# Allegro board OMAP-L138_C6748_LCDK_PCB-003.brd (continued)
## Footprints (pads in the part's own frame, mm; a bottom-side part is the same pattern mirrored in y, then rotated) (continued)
QFN48_25V
  custom 0.058x0.058 smd: 1(-2.75,-3.475) 2(-2.25,-3.475) 3(-1.75,-3.475) 4(-1.25,-3.475) 5(-0.75,-3.475) 6(-0.25,-3.475) 7(0.25,-3.475) 8(0.75,-3.475) 9(1.25,-3.475) 10(1.75,-3.475) 11(2.25,-3.475) 12(2.75,-3.475) 13(3.475,-2.75) 14(3.475,-2.25) 15(3.475,-1.75) 16(3.475,-1.25) 17(3.475,-0.75) 18(3.475,-0.25) 19(3.475,0.25) 20(3.475,0.75) 21(3.475,1.25) 22(3.475,1.75) 23(3.475,2.25) 24(3.475,2.75) 25(2.75,3.475) 26(2.25,3.475) 27(1.75,3.475) 28(1.25,3.475) 29(0.75,3.475) 30(0.25,3.475) 31(-0.25,3.475) 32(-0.75,3.475) 33(-1.25,3.475) 34(-1.75,3.475) 35(-2.25,3.475) 36(-2.75,3.475) 37(-3.475,2.75) 38(-3.475,2.25) 39(-3.475,1.75) 40(-3.475,1.25) 41(-3.475,0.75) 42(-3.475,0.25) 43(-3.475,-0.25) 44(-3.475,-0.75) 45(-3.475,-1.25) 46(-3.475,-1.75) 47(-3.475,-2.25) 48(-3.475,-2.75)
  rect 5.156x5.156 smd: 49(0,0)
RAPC712
  round 4.064 hole 3.556: 1(0,0)
  round 3.683 hole 3.048: 2(-2.997,-4.801) 3(-6.248,0)
RCA4SMD_11X15MM
  round 3.175 hole 1.803: 1(0,0)
  rect 2.54x2.286 smd: 2(0,-6.25) 3(-6.35,-6) 4(6.35,-6)
RJ45-2LED
  round 3.251 hole 3.251 unplated: (8.89,1.27) (8.89,-10.16)
  rect 1.397x1.397 hole 0.889: 1(0,0)
  round 1.397 hole 0.889: 2(2.54,-1.27) 3(0,-2.54) 4(2.54,-3.81) 5(0,-5.08) 6(2.54,-6.35) 7(0,-7.62) 8(2.54,-8.89)
  round 1.524 hole 1.016: 9(-4.826,1.016) 10(-4.826,-1.524) 11(-4.826,-7.366) 12(-4.826,-9.906)
  round 2.54 hole 1.575: 13(5.842,3.302) 14(5.842,-12.192)
SATA
  rect 1.27x1.27 hole 0.762: 1(7.91,0)
  oval 1.016x1.27 hole 0.762: 2(6.64,1.5) 3(5.37,1.5) 5(2.83,1.5) 6(1.56,1.5)
  round 1.27 hole 0.762: 4(4.1,0) 7(0.29,0)
  round 2.032 hole 1.397: 8(10.37,1.5) 9(-2.46,2.5)
SD-MICRO-SCHA5B0300
  rect 0.914x0.457 smd: 1(-7.257,0) 2(-7.257,-0.7) 3(-7.257,-1.4) 4(-7.257,-2.1) 5(7.257,-2.1) 6(7.257,-1.4) 7(7.257,-0.7) 8(7.257,0)
  rect 0.508x0.889 smd: 9(3.775,9.989) 10(-5.975,9.989)
  rect 0.889x2.007 smd: 11(-7.25,7.635) 12(7.25,6.335)
  rect 1.118x1.524 smd: 13(-7.196,-3.365) 14(7.196,-3.365)
  rect 1.194x1.092 smd: 15(-3.425,10.488) 16(2.575,10.488)
SM_OSC_ABM3
  rect 1.9x2.4 smd: 1(-2.05,0) 2(2.05,0)
SMINI6-F3-B
  rect 0.305x0.95 smd: 1(0.65,0.75) 2(0,0.75) 3(-0.65,0.75) 4(-0.65,-0.75) 5(0,-0.75) 6(0.65,-0.75)
SOIC8
  rect 0.635x1.905 smd: 1(-1.905,-2.73) 2(-0.635,-2.73) 3(0.635,-2.73) 4(1.905,-2.73) 5(1.905,2.73) 6(0.635,2.73) 7(-0.635,2.73) 8(-1.905,2.73)
SOIC16
  rect 1.27x0.635 smd: 1(-2.477,4.445) 2(-2.477,3.175) 3(-2.477,1.905) 4(-2.477,0.635) 5(-2.477,-0.635) 6(-2.477,-1.905) 7(-2.477,-3.175) 8(-2.477,-4.445) 9(2.477,-4.445) 10(2.477,-3.175) 11(2.477,-1.905) 12(2.477,-0.635) 13(2.477,0.635) 14(2.477,1.905) 15(2.477,3.175) 16(2.477,4.445)
SOP-DGG48
  rect 0.254x1.651 smd: 1(-5.75,-3.813) 2(-5.25,-3.813) 3(-4.75,-3.813) 4(-4.25,-3.813) 5(-3.75,-3.813) 6(-3.25,-3.813) 7(-2.75,-3.813) 8(-2.25,-3.813) 9(-1.75,-3.813) 10(-1.25,-3.813) 11(-0.75,-3.813) 12(-0.25,-3.813) 13(0.25,-3.813) 14(0.75,-3.813) 15(1.25,-3.813) 16(1.75,-3.813) 17(2.25,-3.813) 18(2.75,-3.813) 19(3.25,-3.813) 20(3.75,-3.813) 21(4.25,-3.813) 22(4.75,-3.813) 23(5.25,-3.813) 24(5.75,-3.813) 25(5.75,3.813) 26(5.25,3.813) 27(4.75,3.813) 28(4.25,3.813) 29(3.75,3.813) 30(3.25,3.813) 31(2.75,3.813) 32(2.25,3.813) 33(1.75,3.813) 34(1.25,3.813) 35(0.75,3.813) 36(0.25,3.813) 37(-0.25,3.813) 38(-0.75,3.813) 39(-1.25,3.813) 40(-1.75,3.813) 41(-2.25,3.813) 42(-2.75,3.813) 43(-3.25,3.813) 44(-3.75,3.813) 45(-4.25,3.813) 46(-4.75,3.813) 47(-5.25,3.813) 48(-5.75,3.813)
SOT23_3
  rect 0.813x1.016 smd: 1(-0.95,-1) 2(0.95,-1) 3(0,1)
STX3500
  round 1.702 hole 1.702 unplated: (-3.75,0) (3.25,0)
  rect 2.21x2.794 smd: 1(-4.85,-3.7) 3(-2.85,3.7)
  rect 2.794x2.794 smd: 2(4.55,-3.7) 4(8.65,0.75)
SWDIP16_340SMD
  rect 1.143x2.54 smd: 1(-8.89,-4.318) 2(-6.35,-4.318) 3(-3.81,-4.318) 4(-1.27,-4.318) 5(1.27,-4.318) 6(3.81,-4.318) 7(6.35,-4.318) 8(8.89,-4.318) 9(8.89,4.318) 10(6.35,4.318) 11(3.81,4.318) 12(1.27,4.318) 13(-1.27,4.318) 14(-3.81,4.318) 15(-6.35,4.318) 16(-8.89,4.318)
SWRST4_177X256LS-1
  round 2.032 hole 1.067: 1(-3.251,-2.248) 2(3.251,-2.248) 3(-3.251,2.248) 4(3.251,2.248)
TP
  round 1.422 hole 1.016: 1(0,0)
unnamed#2
  round 1.016 smd: 1(0,0)
USB5MINI_4SHIELDED_SMD-4
  rect 2.25x0.5 smd: 1(0,1.6) 2(0,0.8) 3(0,0) 4(0,-0.8) 5(0,-1.6)
  rect 3.5x2.05 smd: 6(0.025,4.916) 9(0.025,-4.916)
  rect 4x2.05 smd: 7(-4.225,4.916) 8(-4.225,-4.916)
USB_A_SH
  round 1.651 hole 1.016: 1(0,0) 2(2.499,0) 3(4.501,0) 4(7,0)
  oval 2.032x3.429 hole 1.016x2.413: 5(-3.071,-2.71) 6(10.071,-2.71)
XTAL2_FX135
  rect 1.143x2.032 smd: 1(-1.245,0) 2(1.245,0)
XTAL4_74X83LS_98X126SMD
  rect 1.016x0.889 smd: 1(-1.05,-0.95) 2(1.05,-0.95) 3(1.05,0.95) 4(-1.05,0.95)

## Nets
1V2_LDO: C17.1 C66.1 C67.1 C68.1 C69.1 FB4.1 R20.1 U3.16(VLDO1) U7.M2(SATA_VDD0) U7.M12(USB_CVDD12) U7.N4(SATA_VDD3) U7.P1(SATA_VDD1) U7.P2(SATA_VDD2)
1V8_LDO: C16.2 C64.1 C65.1 R18.2 U3.14(VLDO2) U7.N14(USB0_VDDA18) U7.P3(SATA_VDDR) U7.P14(USB1_VDDA18)
5V_IN: D1.3(C) D2.2(ANODE) J1.1 J8.9 J14.1 J14.2(21) J15.24(32) J15.33(17) J15.45 J15.46 J16.4 J16.5 P1.1 P1.2 R270.1 U2.1(IN1) U2.7(IN0)
GND_EARTH: FB5.1 J2.6(G3) J2.7(G2) J2.8(G5) J2.9(G4) J3.6(G3) J3.7(G2) J3.8(G5) J3.9(G4) J4.11(GND3) J4.12(GND4) J4.13(GND5) J4.14(GND6) J4.15(GND7) J4.16(GND8) J5.5(SHELD1) J5.6(PAD4) J7.8(MH1) J7.9(MH2)
VCC_1V2A: FB4.2 U7.L15(VDDA12_PLL0) U7.N15(VDDA12_PLL1)
VCC_1V3D: C11.1 C12.1 C70.1 C71.1 C72.1 C73.1 C74.1 C75.1 C76.1 C77.1 C78.1 C79.1 C80.1 R5.2(I2) R27.1 R29.1 TP2.1 U7.E5(RVDD-0) U7.E15(CVDD-0) U7.G7(CVDD-1) U7.G8(CVDD-2) U7.G13(CVDD-3) U7.H6(CVDD-4) U7.H7(CVDD-5) U7.H10(CVDD-6) U7.H11(CVDD-7) U7.H12(CVDD-8) U7.H13(CVDD-9) U7.H14(RVDD-1) U7.J6(CVDD-10) U7.J12(CVDD-11) U7.K6(CVDD-12) U7.K12(CVDD-13) U7.L12(CVDD-14) U7.M8(CVDD-15) U7.M9(CVDD-16) U7.N7(RVDD-2) U7.N8(CVDD-17) U7.T19(VPP(RSV))
VCC_1V8D: C5.1 C6.1 C35.1 C36.1 C37.1 C38.1 C39.1 C40.1 C41.1 C42.1 C43.1 C44.1 C45.1 C94.1 C101.2 C102.2 C103.2 C119.2 C120.1 C121.1 C122.1 C123.1 C124.1 C125.1 C126.1 C127.1 C128.1 C129.1 C130.1 C131.1 C132.1 C133.1 C134.1 C135.1 C152.1 C153.1 C154.1 C155.1 C156.1 C170.1 C171.1 C204.1 C207.2 C208.2 C210.1 C216.2 FB10.1 FB15.2 P2.2 R2.2(I2) R28.1 R98.2 R99.2 R100.2 R123.1 TP4.1 U7.F14(DVDD18-0) U7.G6(DVDD18-1) U7.G10(DVDD18-2) U7.G11(DVDD18-3) U7.G12(DVDD18-4) U7.J13(DVDD18-5) U7.K5(DVDD18-6) U7.L6(DVDD18-7) U7.N6(DVDD18-8) U7.N9(DVDD18-9) U7.N10(DVDD18-10) U7.P7(DVDD18-11) U7.P8(DVDD18-12) U7.P9(DVDD18-13) U7.P10(DVDD18-14) U7.P13(DVDD18-15) U7.R7(DVDD18-16) U7.R8(DVDD18-17) U7.R9(DVDD18-18) U7.R13(DVDD18-19) U12.1(VCCA) U13.12(DVDD) U14.31(VCCA1) U14.42(VCCA2) U17.A1(VDD5) U17.A9(VDDQ10) U17.C1(VDDQ9) U17.C3(VDDQ8) U17.C7(VDDQ7) U17.C9(VDDQ6) U17.E1(VDD4) U17.E9(VDDQ4) U17.G1(VDDQ3) U17.G3(VDDQ5) U17.G7(VDDQ2) U17.G9(VDDQ1) U17.J1(VDDL) U17.J9(VDD1) U17.M9(VDD3) U17.R1(VDD2) U21.31(DVDD4) U21.41(DVDD5) U21.55(DVDD6) U21.67(DVDD7) U24.1(VCCA) U25.3(VCCA) U25.6(OE) U26.A2(VDDA) U26.E4(VDD) U28.1(VCCA) U28.5(DIR)
VCC_3V3A: C199.1 C200.1 C201.1 FB18.2 R165.1 R166.1 R167.1 R168.1 R185.2 U23.1(VDD33A2) U23.27(VDD33A1)
VCC_3V3ADAC: C97.2 C98.1 C107.1 FB6.2 U13.40(AVDD1) U13.44(AVDD2)
VCC_3V3AFLA: C138.1 C139.1 C140.1 C145.1 FB8.2 R137.2 R139.2 U18.D3(VCC.1) U18.G4(VCC.3) U18.H8(VCC.2) U18.J6(VCC.4)
VCC_3V3ASATA: C27.1 C28.1 C29.1 C30.1 FB3.1 U9.9(VCC_VCO) U9.16(VCC_PLL2) U9.18(VCC_PLL1)
VCC_3V3D: C4.1 C13.1 C14.1 C31.1 C32.1 C33.1 C50.1 C51.1 C52.1 C53.1 C54.1 C55.1 C56.1 C57.1 C58.1 C59.1 C60.1 C61.1 C62.1 C63.1 C81.1 C82.1 C86.1 C95.2 C96.2 C99.2 C100.2 C106.2 C118.1 C146.1 C149.1 C150.1 C151.1 C180.1 C185.1 C193.1 C205.2 C206.2 C209.2 C215.1 C217.1 FB3.2 FB6.1 FB8.1 FB9.1 FB14.2 FB16.2 FB18.1 J4.4(VDD) J14.43 J14.44 J15.1 J15.2(21) J16.1 J16.2 J16.3 R4.1(I1) R34.1 R35.1 R36.1 R41.2 R44.1 R45.1 R46.1 R47.1 R48.1 R49.1 R50.1 R51.1 R55.1 R57.1 R58.1 R59.1 R62.1 R63.1 R64.2 R65.1 R73.2 R74.1 R75.2 R80.1 R86.1 R87.2 R88.2 R89.1 R96.1 R97.1 R103.1 R104.1 R105.1 R106.1 R141.2 R146.2 R147.1 R148.2 R160.2 R163.1 R169.1 R171.1 R176.1 R189.2 R192.2 R193.2 R194.2 R203.1 R220.1 R221.1 R244.1 R245.1 R246.1 R247.1 R248.1 R249.1 R250.1 R251.1 R252.1 R257.1 R258.2 R259.1 R260.2 R261.1 R262.1 R263.1 R275.1 R276.1 R277.1 R278.1 R279.1 R280.1 TP5.1 U1.2(VDD) U7.E14(DVDD3318-B-0) U7.F5(DVDD3318-A-0) U7.F6(DVDD3318-B-1) U7.F7(DVDD3318-B-2) U7.F8(DVDD3318-B-3) U7.F10(DVDD3318-B-4) U7.F11(DVDD3318-B-5) U7.F12(DVDD3318-B-6) U7.F13(DVDD3318-B-7) U7.F15(DVDD3318-A-1) U7.G5(DVDD3318-A-2) U7.G9(DVDD3318-B-8) U7.G14(DVDD3318-A-3) U7.G15(DVDD3318-A-4) U7.H5(DVDD3318-A-5) U7.J5(DVDD3318-C-0) U7.J14(DVDD3318-B-9) U7.K13(DVDD3318-C-1) U7.K15(DVDD3318-B-10) U7.L4(DVDD3318-C-2) U7.L13(DVDD3318-C-3) U7.M13(DVDD3318-C-4) U7.N13(DVDD3318-C-5) U7.N18(USB0_VDDA33) U7.P5(DVDD3318-C-6) U7.P6(DVDD3318-C-7) U7.P12(DVDD3318-C-8) U7.P15(USB1_VDDA33) U7.R4(DVDD3318-C-9) U9.4(VCC_OUT) U9.20(VCC_IN) U11.5(VCC) U12.8(VCCB) U14.7(VCCB1) U14.18(VCCB2) U15.8(VCCB) U16.3(VCCA) U16.6(OE) U21.38(IOVDD1) U21.48(IOVDD2) U21.61(IOVDD3) U23.12(VDDIO) U24.8(VCCB) U25.7(VCCB) U26.E5(VDDIO) U27.5(VCC) U28.6(VCCB) Y3.1(STANDBY#) Y3.4(VDD) Y5.4(VCC)
VCC_5VD: C7.1 C8.1 C9.1 C10.1 C18.1 C104.1 C141.1 DN1.2 DN2.2 J5.1(P1) R3.1 R9.1 R10.2 R11.2 R12.2 R13.2 R15.1 R22.2 R23.2 R24.2 R26.2 R120.1 R121.1 R210.1 R211.1 TP3.1 U3.4(VINDCDC3) U3.5(VINDCDC1) U3.9(DEFDCDC1) U3.15(VINLDO) U3.28(VINDCDC2) U4.7(IN4) U4.14(OUT2) U5.6(OUT3) U5.7(OUT2) U5.8(OUT1) U6.5(VCC) U15.1(VCCA) U16.7(VCCB)
VCC_5VD_IN: C1.1 C2.1 C3.1 R21.1 TP1.1 U2.4(OUT0) U2.5(OUT1) U4.8(E\N\3\) U4.13(E\N\2\) U5.2(IN1) U5.3(IN2)
VCC_AIC3106_1V8D: C181.1 C186.1 FB15.1 U22.36(DVDD.1)
VCC_AIC3106_3V3A: C182.1 C183.1 C184.1 FB14.1 U22.25(AVDD_DAC)
VCC_AIC3106_3V3D: C187.1 C188.1 C189.1 C190.1 C191.1 FB16.1 U22.16(DRVDD.1) U22.17(DRVDD.2) U22.24(DRVDD.3) U22.44(IOVDD)
VCC_USB0_IN: J2.1(VB) R54.2 U4.6(IN3) U4.10(OUT4)
VCC_USB0_IN_K: C19.1 R25.1 U4.3(IN2) U4.11(OUT3) U5.4(E\N\)
VDD_ALIVE: C15.1 TP8.1 U3.12(VDD_ALIVE)
ACTIVITYLED: R181.1 R188.1 U23.3(LED1/REGOFF)
AES_ADDR/FS: R205.2 U26.D5(I2C_ADDR/FS)
AES_CLK: R200.2 R201.2 U26.E2(SCL/CLK)
AES_DATA: R202.2 R204.2 U26.E3(SDA/DX)
AIC_BCLK: J15.41 R95.2 U22.38(BCLK)
AIC_MCLK: J15.39(20) R164.1 U7.A3(AHCLKX/USB_REFCLKIN/UART1_CTSN/) U22.37(MCLK)
AIC_MCLK_K: R164.2 Y5.3(OUT)
AIC_WCLK: J15.37(19) R94.2 U22.39(WCLK)
AUDIO_IN_AXR8/ECAP1_APWM2: J15.32(36) U7.E4(AXR8/CLKS1/ECAP1_APWM1/GPIO0[0])
AUDIO_LEFT: C178.2 J10.6(4L) R156.1
AUDIO_RIGHT: C179.2 J10.5(1L) R157.1
AVID/GPIO: TP14.1 U21.36(AVID/GPIO)
AXR0/ECAP0_APWM0/MII_TXD0: R90.2 U23.22(TXD0)
AXR1/MII_TXD1: R93.2 U23.23(TXD1)
AXR2/MII_TXD2: R92.2 U23.24(TXD2)
AXR3/MII_TXD3: R91.2 U23.25(TXD3)
AXR4/MII_COL: R183.1 R280.2 U7.D1(AXR4/MCBSP0_FSR0/GPIO1[12]/MII_)
AXR5/MII_TXCLK: R182.1 U7.D3(AXR5/MCBSP0_CLKX0/GPIO1[13]/MII)
AXR6/MII_TXEN: U7.C1(AXR6/MCBSP0_CLKR0/GPIO1[14]/MII) U23.21(TX_EN)
AXR7/EPWM1TZ0: J15.28(34) U7.D2(AXR7/EPWMN1_TZ[0]/GPIO1[15])
AXR13: R161.1 U7.B3(AXR13/MCBSP1_CLKX1/GPIO0[5]) U22.40(DIN)
AXR14: U7.B4(AXR14/MCBSP1_CLKR1/GPIO0[6]) U22.41(DOUT)
AXR15/EPWMN0_TZ0/ECAP2_APWM2: J15.36(38) U7.A4(AXR15/EPWMN0_TZ[0]/ECAP2_APWM2/)
BRD_RSTN: U1.7(\R\E\S\E\T) U7.K14(RESETN) U11.6(C)
CAM_CLK: J16.9 R81.2 U7.W14(VPIF_CLKIN0/UHPI_HCSN/GPIO6[7]/) U27.4(Y)
CBUS0: U8.22(CBUS0)
CBUS1: U8.21(CBUS1)
CBUS2: U8.10(CBUS2)
CBUS4: U8.9(CBUS4)
CPU_DDR_A0: R230.1 U7.U7(DDR_A_00)
CPU_DDR_A1: R231.1 U7.T7(DDR_A_01)
CPU_DDR_A2: R232.1 U7.W6(DDR_A_02)
CPU_DDR_A3: R233.1 U7.V6(DDR_A_03)
CPU_DDR_A4: R234.1 U7.U5(DDR_A_04)
CPU_DDR_A5: R235.1 U7.V5(DDR_A_05)
CPU_DDR_A6: R236.1 U7.W5(DDR_A_06)
CPU_DDR_A7: R237.1 U7.U6(DDR_A_07)
CPU_DDR_A8: R238.1 U7.U4(DDR_A_08)
CPU_DDR_A9: R239.1 U7.T6(DDR_A_09)
CPU_DDR_A10: R240.1 U7.W4(DDR_A_10)
CPU_DDR_A11: R241.1 U7.T4(DDR_A_11)
CPU_DDR_A12: R242.1 U7.V4(DDR_A_12)
CPU_DDR_A13: R243.1 U7.T5(DDR_A_13)
CPU_DDR_BA0: R265.1 U7.V8(DDR_BA_0)
CPU_DDR_BA1: R266.1 U7.T9(DDR_BA_1)
CPU_DDR_BA2: R267.1 U7.U8(DDR_BA_2)
CPU_DDR_CASN: R127.1 U7.U9(DDR_CASN)
CPU_DDR_CKE: R130.1 U7.V7(DDR_CKE)
CPU_DDR_CLKN: R132.1 U7.W7(DDR_CLKN)
CPU_DDR_CLKP: R131.1 U7.W8(DDR_CLKP)
CPU_DDR_CSN: R126.1 U7.V9(DDR_CSN)
CPU_DDR_DQ0: R107.2 U7.U15(DDR_D_00)
CPU_DDR_DQ1: R108.2 U7.U14(DDR_D_01)
CPU_DDR_DQ2: R109.2 U7.V14(DDR_D_02)
CPU_DDR_DQ3: R110.2 U7.U13(DDR_D_03)
CPU_DDR_DQ4: R111.2 U7.V13(DDR_D_04)
CPU_DDR_DQ5: R112.2 U7.V12(DDR_D_05)
CPU_DDR_DQ6: R115.2 U7.W12(DDR_D_06)
CPU_DDR_DQ7: R116.2 U7.W11(DDR_D_07)
CPU_DDR_DQ8: R138.2 U7.T13(DDR_D_08)
CPU_DDR_DQ9: R140.2 U7.T11(DDR_D_09)
CPU_DDR_DQ10: R224.2 U7.T10(DDR_D_10)
CPU_DDR_DQ11: R225.2 U7.T12(DDR_D_11)
CPU_DDR_DQ12: R226.2 U7.U10(DDR_D_12)
CPU_DDR_DQ13: R227.2 U7.V10(DDR_D_13)
CPU_DDR_DQ14: R228.2 U7.U11(DDR_D_14)
CPU_DDR_DQ15: R229.2 U7.W10(DDR_D_15)
CPU_DDR_DQM0: R136.1 U7.W13(DDR_DQM_0)
CPU_DDR_DQM1: R135.1 U7.R10(DDR_DQM_1)
CPU_DDR_DQS0: R134.1 U7.T14(DDR_WEN_DQS_0)
CPU_DDR_DQS1: R133.1 U7.V11(DDR_WEN_DQS_1)
CPU_DDR_RASN: R128.1 U7.W9(DDR_RASN)
CPU_DDR_WEN: R129.1 U7.T8(DDR_WEN)
CTS#: U8.8(CTS#)
CVI_AGND: BH1.2(N) C1.2 C2.2 C3.2 C4.2 C5.2 C6.2 C7.2 C8.2 C9.2 C10.2 C11.2 C12.2 C13.2 C14.2 C15.2 C16.1 C17.2 C18.2 C19.2 C20.2 C21.2 C22.2 C23.2 C24.2 C25.2 C26.2 C27.2 C28.2 C29.2 C30.2 C31.2 C32.2 C33.2 C35.2 C36.2 C37.2 C38.2 C39.2 C40.2 C41.2 C42.2 C43.2 C44.2 C45.2 C47.2 C48.1 C49.1 C50.2 C51.2 C52.2 C53.2 C54.2 C55.2 C56.2 C57.2 C58.2 C59.2 C60.2 C61.2 C62.2 C63.2 C64.2 C65.2 C66.2 C67.2 C68.2 C69.2 C70.2 C71.2 C72.2 C73.2 C74.2 C75.2 C76.2 C77.2 C78.2 C79.2 C80.2 C81.2 C82.2 C83.2 C86.2 C94.2 C95.1 C96.1 C97.1 C98.2 C99.1 C100.1 C101.1 C102.1 C103.1 C104.2 C106.1 C108.1 C109.1 C111.1 C112.1 C114.1 C115.1 C116.1 C118.2 C120.2 C121.2 C122.2 C123.2 C124.2 C125.2 C126.2 C127.2 C128.2 C129.2 C130.2 C131.2 C132.2 C133.2 C134.2 C135.2 C136.1 C137.2 C138.2 C139.2 C140.2 C141.2 C142.2 C143.2 C144.2 C145.2 C146.2 C147.2 C148.2 C149.2 C150.2 C151.2 C152.2 C153.2 C154.2 C155.2 C156.2 C157.2 C158.2 C159.2 C160.2 C161.2 C163.2 C164.2 C165.2 C166.2 C167.2 C168.2 C169.2 C170.2 C171.2 C174.1 C177.1 C180.2 C181.2 C182.2 C183.2 C184.2 C185.2 C186.2 C187.2 C188.2 C189.2 C190.2 C191.2 C193.2 C194.2 C196.2 C197.2 C198.2 C199.2 C200.2 C201.2 C202.1 C203.1 C204.2 C205.1 C206.1 C207.1 C208.1 C209.1 C210.2 C211.1 C212.1 C213.1 C214.1 C215.2 C216.1 C217.2 D1.1(A) D3.1(CATHODE) D8.1(ANODE) DN1.1 DN2.1 FB1.1 FB5.2 J1.2 J1.3 J2.5(G1) J3.5(G1) J4.6(VSS) J4.9(GND) J5.4(P4) J6.4 J6.8 J6.10 J6.12 J7.1 J7.4 J7.7 J8.5 J8.6 J8.7 J8.8 J8.10 J8.16 J8.17 J9.1(SHIELD1) J9.3(G1) J9.4(G2) J10.1(5U) J10.4(5L) J11.1(SHIELD) J11.4(TIPB) J13.4(GND1) J13.5(GND2) J13.11(YELC) J14.19(10) J14.20(30) J14.45 J14.46 J15.22(31) J15.26(33) J15.30(35) J15.34(37) J15.35(18) J15.38(39) J15.42 J15.43 J16.6 J16.8 J16.10 J16.25 J16.26 JP1.1 P1.19 P1.20 P2.19 P2.20 Q1.2(EMITTER) Q2.2(EMITTER) Q3.2(EMITTER) Q4.2(EMITTER) Q5.1(4) Q5.4 Q6.1(4) Q6.4 R7.2 R8.2 R14.1 R16.1 R17.1 R19.1 R21.2 R25.2 R33.2 R37.2 R38.2 R39.2 R40.2 R42.2 R52.2 R61.2 R66.1 R67.1 R76.1 R77.1 R78.1 R79.1 R82.1 R83.1 R84.1 R85.1 R101.1 R102.1 R113.2 R114.2 R117.2 R118.1 R119.1 R122.2 R124.2 R125.2 R143.1 R145.1 R149.1 R153.1 R155.1 R156.2 R157.2 R158.1 R159.1 R161.2 R162.1 R170.2 R180.1 R186.2 R188.2 R195.1 R196.1 R197.1 R198.2 R199.2 R207.2 R212.2 R213.2 R222.2 R223.2 R253.1 R254.1 R255.1 R256.1 R264.2 R273.2 R274.1 S1.3(B1) S1.4(B2) TP6.1 TP7.1 U1.3(GND) U2.2(GND) U2.6(E\N\) U3.2(PGND3) U3.7(PGND1) U3.22(DEFDCDC2) U3.26(PGND2) U4.1(GNDA) U4.5(GNDB) U5.1(GND) U5.9(POWERPAD) U6.3(GND) U7.A19(VSS-0) U7.H1(SATA-VSS-5) U7.H2(SATA-VSS-4) U7.H8(VSS-1) U7.H9(VSS-2) U7.H15(VSS-3) U7.J7(VSS-4) U7.J8(VSS-5) U7.J9(VSS-6) U7.J10(VSS-7) U7.J11(VSS-8) U7.K1(SATA-VSS-3) U7.K2(SATA-VSS-2) U7.K7(VSS-9) U7.K8(VSS-10) U7.K9(VSS-11) U7.K10(VSS-12) U7.K11(VSS-13) U7.L3(SATA-VSS-1) U7.L5(VSS-14) U7.L7(VSS-15) U7.L8(VSS-16) U7.L9(VSS-17) U7.L10(VSS-18) U7.L11(VSS-19) U7.L18(OSCVSS) U7.M1(SATA-VSS-0) U7.M4(VSS-20) U7.M5(VSS-21) U7.M6(VSS-22) U7.M7(VSS-23) U7.M10(VSS-24) U7.M11(VSS-25) U7.M15(VSSA12_PLL1) U7.M17(VSSA12_PLL0) U7.N5(VSS-26) U7.N11(VSS-27) U7.N12(VSS-28) U7.P11(VSS-29) U8.4(GND1) U8.17(GND2) U8.20(GND3) U8.24(AGND) U8.26(TEST) U8.33(GND) U9.22(GND1) U9.33(GND) U11.2(GND) U12.4(GND) U12.5(DIR) U13.11(DVSS) U13.42(AVSS1) U13.46(AVSS2) U13.49(PWR_PAD) U14.1(DIR1) U14.4(GND1) U14.10(GND2) U14.15(GND3) U14.21(GND4) U14.24(DIR2) U14.25(O\E\1\) U14.28(GND5) U14.34(GND6) U14.39(GND7) U14.45(GND8) U14.48(O\E\2\) U15.4(GND) U15.5(DIR) U16.2(GND) U17.A3(VSS5) U17.A7(VSSQ10) U17.B2(VSSQ9) U17.B8(VSSQ8) U17.D2(VSSQ7) U17.D8(VSSQ6) U17.E3(VSS4) U17.E7(VSSQ5) U17.F2(VSSQ4) U17.F8(VSSQ3) U17.H2(VSSQ2) U17.H8(VSSQ1) U17.J3(VSS3) U17.J7(VSSDL) U17.N1(VSS2) U17.P9(VSS1) U18.C5(VSS.1) U18.F7(VSS.3) U18.K3(VSS.2) U18.K8(VSS.4) U21.3(CH1_A33GND) U21.6(CH2_A33GND) U21.10(CH2_A18GND) U21.13(A18GND_REF) U21.24(A18GND) U21.26(AGND) U21.27(DGND1) U21.32(DGND2) U21.39(IOGND2) U21.42(DGND3) U21.49(IOGND3) U21.56(DGND4) U21.62(IOGND1) U21.68(DGND5) U21.77(PLL_A18GND) U21.79(CH1_A18GND) U21.81(THERMAL_LAND) U22.15(AVSS_ADC) U22.20(DRVSS.1) U22.21(DRVSS.2) U22.26(AVSS_DAC) U22.42(DVSS) U22.49(TPAD) U23.33(VSS/FLAG) U24.4(GND) U24.5(DIR) U25.2(GND) U26.A3(VSSA) U26.C2(GND1) U26.C4(GND2) U27.3(GND) U28.2(GND) Y1.1 Y3.2(GND) Y5.2(GND)
CVIDEO_DIN0: J16.24 R244.2 U7.W19(VPIF_DIN0/UHPI_HD8/UPP_CH1_D8/R) U21.52(Y_2)
CVIDEO_DIN1: J16.23 R245.2 U7.W18(VPIF_DIN1/UHPI_HD9/UPP_CH1_D9/R) U21.51(Y_3)
CVIDEO_DIN2: J16.22 R246.2 U7.W17(VPIF_DIN2/UHPI_HD10/UPP_CH1_D10) U21.50(Y_4)
CVIDEO_DIN3: J16.21 R247.2 U7.V17(VPIF_DIN3/UHPI_HD11/UPP_CH1_D11) U21.47(Y_5)
CVIDEO_DIN4: J16.20 R248.2 U7.W16(VPIF_DIN4/UHPI_HD12/UPP_CH1_D12) U21.46(Y_6)
CVIDEO_DIN5: J16.19 R249.2 U7.R14(VPIF_DIN5/UHPI_HD13/UPP_CH1_D13) U21.45(Y_7)
CVIDEO_DIN6: J16.18 R250.2 U7.V16(VPIF_DIN6/UHPI_HD14/UPP_CH1_D14) U21.44(Y_8)
CVIDEO_DIN7: J16.17 R251.2 U7.U18(VPIF_DIN7/UHPI_HD15/UPP_CH1_D15) U21.43(Y_9)
CVIDEO_DIN8: J16.16 U7.P17(VPIF_DIN8/UHPI_HD0/UPP_CH1_D0/G)
CVIDEO_DIN9: J16.15 U7.R15(VPIF_DIN9/UHPI_HD1/UPP_CH1_D1)
CVIDEO_DIN10: J16.14 U7.R19(VPIF_DIN10/UHPI_HD2/UPP_CH1_D2)
CVIDEO_DIN11: J16.13 U7.R18(VPIF_DIN11/UHPI_HD3/UPP_CH1_D3)
CVIDEO_DIN14_HSYNC: J16.12 U7.V19(VPIF_DIN14_HSYNC/UHPI_HD6/UPP_C)
CVIDEO_DIN15_VSYNC: J16.11 U7.V18(VPIF_DIN15_VSYNC/UHPI_HD7/UPP_C)
DCD#: U8.7(DCD#)
DDC_SCL: DN2.3 J8.15 R120.2 U16.8(B1)
DDC_SDA: DN1.3 J8.12 R121.2 U16.1(B2)
DDR_A0: R230.2 U17.M8(A0)
DDR_A1: R231.2 U17.M3(A1)
DDR_A2: R232.2 U17.M7(A2)
DDR_A3: R233.2 U17.N2(A3)
DDR_A4: R234.2 U17.N8(A4)
DDR_A5: R235.2 U17.N3(A5)
DDR_A6: R236.2 U17.N7(A6)
DDR_A7: R237.2 U17.P2(A7)
DDR_A8: R238.2 U17.P8(A8)
DDR_A9: R239.2 U17.P3(A9)
DDR_A10: R240.2 U17.M2(A10)
DDR_A11: R241.2 U17.P7(A11)
DDR_A12: R242.2 U17.R2(A12)
DDR_A13: R243.2 U17.R8(RFU1)
DDR_BA0: R265.2 U17.L2(BA0)
DDR_BA1: R266.2 U17.L3(BA1)
DDR_BA2: R267.2 U17.L1(BA2)
DDR_CASN: R127.2 U17.L7(CASN)
DDR_CKE: R130.2 U17.K2(CKE)
DDR_CLKN: R132.2 U17.K8(CKN)
DDR_CLKP: R131.2 U17.J8(CK)
DDR_CSN: R126.2 U17.L8(CSN)
DDR_DQ0: R107.1 U17.G8(DQ0)
DDR_DQ1: R108.1 U17.G2(DQ1)
DDR_DQ2: R109.1 U17.H7(DQ2)
DDR_DQ3: R110.1 U17.H3(DQ3)
DDR_DQ4: R111.1 U17.H1(DQ4)
DDR_DQ5: R112.1 U17.H9(DQ5)
DDR_DQ6: R115.1 U17.F1(DQ6)
DDR_DQ7: R116.1 U17.F9(DQ7)
DDR_DQ8: R138.1 U17.C8(DQ8)
DDR_DQ9: R140.1 U17.C2(DQ9)
DDR_DQ10: R224.1 U17.D7(DQ10)
DDR_DQ11: R225.1 U17.D3(DQ11)
DDR_DQ12: R226.1 U17.D1(DQ12)
DDR_DQ13: R227.1 U17.D9(DQ13)
DDR_DQ14: R228.1 U17.B1(DQ14)
DDR_DQ15: R229.1 U17.B9(DQ15)
DDR_DQGATE0: R53.1 U7.R11(DDR_DQGATE0)
DDR_DQGATE1: R53.2 U7.R12(DDR_DQGATE1)
DDR_DQM0: R136.2 U17.F3(LDM)
DDR_DQM1: R135.2 U17.B3(UDM)
DDR_DQS0: R134.2 U17.F7(LDQS)
DDR_DQS1: R133.2 U17.B7(UDQS)
DDR_RASN: R128.2 U17.K7(RASN)
DDR_VREF: C119.1 C136.2 R123.2 R124.1 U7.R6(DDR_VREF) U17.J2(VREF)
DDR_WEN: R129.2 U17.K3(WEN)
DSP_CLKOUT: R60.1 TP10.1
DSP_RSTOUTN: U7.T17(RESETOUTN/UHPI_HASN/GPIO6[15]) U11.1(A)
DSR#: U8.6(DSR#)
DTR#: U8.31(DTR#)
EMA_A0: J14.21(11) U7.C14(EMA_A_0/GPIO5[0])
EMA_A1: J14.22(31) U7.D15(EMA_A_1/GPIO5[1]) U18.C4(ALE)
EMA_A2: J14.23(12) U7.B14(EMA_A_2/GPIO5[2]) U18.D5(CLE)
EMA_A3: J14.24(32) U7.D14(EMA_A_3/GPIO5[3])
EMA_A4: J14.25(13) U7.A14(EMA_A_4/GPIO5[4])
EMA_A5: J14.26(33) U7.C13(EMA_A_5/GPIO5[5])
EMA_A6: J14.27(14) U7.E13(EMA_A_6/GPIO5[6])
EMA_A7: J14.28(34) U7.B13(EMA_A_7/GPIO5[7])
EMA_A8: J14.29(15) U7.A13(EMA_A_8/GPIO5[8])
EMA_A9: J14.30(35) U7.D12(EMA_A_9/GPIO5[9])
EMA_A10: J14.31(16) U7.C12(EMA_A_10/GPIO5[10])
EMA_A11: J14.32(36) U7.B12(EMA_A_11/GPIO5[11])
EMA_A12: J14.33(17) U7.D13(EMA_A_12/GPIO5[12])
EMA_BA_0: J14.37(19) U7.C15(EMA_BA_0/GPIO2[8])
EMA_BA_1: J14.35(18) U7.A15(EMA_BA_1/GPIO2[9])
EMA_CLK: J14.42 U7.B7(EMA_CLK/GPIO2[7])
EMA_CSN_2: J14.40 R103.2 U7.B17(EMA_CSN_2/GPIO3[15])
EMA_CSN_3: R106.2 U7.A17(EMA_CSN_3/GPIO3[14]) U18.C6(\\C\E)
EMA_CSN_4: J15.7(4) U7.F9(EMA_CSN_4/GPIO3[13])
EMA_CSN_5: J15.3(2) U7.B16(EMA_CSN_5/GPIO3[12])
EMA_D0: J14.3(2) U7.C9(EMA_D_0/GPIO4[8]) U18.H4(I/O00)
EMA_D1: J14.4(22) U7.A8(EMA_D_1/GPIO4[9]) U18.J4(I/O01)
EMA_D2: J14.5(3) U7.B8(EMA_D_2/GPIO4[10]) U18.K4(I/O02)
EMA_D3: J14.6(23) U7.E8(EMA_D_3/GPIO4[11]) U18.K5(I/O03)
EMA_D4: J14.7(4) U7.B5(EMA_D_4/GPIO4[12]) U18.K6(I/O04)
EMA_D5: J14.8(24) U7.E7(EMA_D_5/GPIO4[13]) U18.J7(I/O05)
EMA_D6: J14.9(5) U7.C6(EMA_D_6/GPIO4[14]) U18.K7(I/O06)
EMA_D7: J14.10(25) U7.D7(EMA_D_7/GPIO4[15]) U18.J8(I/O07)
EMA_D8: J14.11(6) U7.E10(EMA_D_8/GPIO3[0]) U18.H3(I/O08)
EMA_D9: J14.12(26) U7.D9(EMA_D_9/GPIO3[1]) U18.J3(I/O09)
EMA_D10: J14.13(7) U7.A7(EMA_D_10/GPIO3[2]) U18.H5(I/O10)
EMA_D11: J14.14(27) U7.D6(EMA_D_11/GPIO3[3]) U18.J5(I/O11)
EMA_D12: J14.15(8) U7.A6(EMA_D_12/GPIO3[4]) U18.H6(I/O12)
EMA_D13: J14.16(28) U7.B6(EMA_D_13/GPIO3[5]) U18.G6(I/O13)
EMA_D14: J14.17(9) U7.C7(EMA_D_14/GPIO3[6]) U18.H7(I/O14)
EMA_D15: J14.18(29) U7.E6(EMA_D_15/GPIO3[7]) U18.G7(I/O15)
EMA_OEN: J14.41 R105.2 U7.B15(EMA_OEN/GPIO3[10]) U18.D4(\\R\E)
EMA_WAIT0: R137.1 U7.B18(EMA_WAIT_0/GPIO3[8]) U18.C8(R/B\)
EMA_WAIT1: J14.34(37) U7.B19(EMA_WAIT_1/GPIO2[1])
EMA_WEN: J14.39(20) R104.2 U7.B9(EMA_WEN/GPIO3[11]) U18.C7(\\W\E)
EMA_WEN_DQM_0: J14.38(39) U7.C8(EMA_WEN_DQM_0/GPIO2[3])
EMA_WEN_DQM_1: J14.36(38) U7.A5(EMA_WEN_DQM_1/GPIO2[2])
EMU0: J6.13 R63.2 R67.2 U7.J16(EMU0)
EMU1: J6.14 R62.2 R66.2 U7.K16(EMU1)
EN_DCDC1: Q2.3(COLLECTOR) R23.1 U3.20(EN_DCDC1)
EN_DCDC2: Q1.3(COLLECTOR) R22.1 U3.19(EN_DCDC2)
ENET_RXN: C194.1 J13.8(RD-) R165.2 U23.30(RXN)
ENET_RXP: C137.1 J13.7(RD+) R166.2 U23.31(RXP)
ENET_TXN: C196.1 J13.2(TD-) R167.2 U23.28(TXN)
ENET_TXP: C197.1 J13.1(TD+) R168.2 U23.29(TXP)
GLCO/I2CA: R148.1 R149.2 U21.37(GLCO/I2CA)
GPIO: TP12.1 U21.35(GPIO)
GPIO0-1: R257.2 SW1.5(A5) U7.C3(ARX9/MCBSP1_DX1/GPIO0[1])
GPIO0-2: R258.1 SW1.6(A6) U7.D4(ARX10/MCBSP1_DR1/GPIO0[2])
GPIO0-3: R259.2 SW1.7(A7) U7.C5(ARX11/MCBSP1_FSX1/GPIO0[3])
GPIO0-4: R260.1 SW1.8(A8) U7.C4(ARX12/MCBSP1_FSR1/GPIO0[4])
GPIO0-9: Q5.5 R213.1 U7.D5(AMUTE/UART2_RTSN/GPIO0[9])
GPIO2-4: R220.2 S2.3(B1) S2.4(B2) U7.A9(EMA_CASN/GPIO2[4])
GPIO2-5: R221.2 S3.3(B1) S3.4(B2) U7.A16(EMA_RASN/GPIO2[5])
GPIO2-6: U7.D8(EMA_SDCKE/GPIO2[6]) U28.4(B)
GPIO2-12: Q5.2(5) R212.1 U7.H16(SPI1_ENAN/GPIO2[12])
GPIO4-0: J4.10(CD) R44.2 U7.E12(EMA_A_16/MMCSD0_D5/GPIO4[0])
GPIO6-8: U7.T15(UHPI_HRWN/UPP_CH1_WAIT/GPIO6[8]) U26.D3(INT)
GPIO6-9: R194.1 R197.2 U7.U16(UHPI_HHWIL/UPP_CH1_ENABLE/GPIO6)
GPIO6-10: R193.1 R196.2 U7.W15(UHPI_HCNTL1/UPP_CH1_START/GPIO6)
GPIO6-11: R192.1 R195.2 U7.U17(UHPI_HCNTL0/UPP_CH1_CLK/GPIO6[1)
GPIO8-10: J15.20(30) U7.F2(MMCSD1_D6/LCD_MCLK/GPIO8[10])
GPIO8-12: J15.16(28) U7.G3(UPP_CH0_WAIT/GPIO8[12])
HS/CS/GPIO: TP11.1 U21.72(HS/CS/GPIO)
INTN: R187.1 U7.A1(ACLKR/GPIO0[15])
INTREQ: TP15.1 U21.30(INTREQ)
LAN_XTAL1: R190.1 R191.1 U23.5(CLKIN/XTAL1)
LAN_XTAL2: C203.2 R191.2 U23.4(XTAL2) Y6.1
LCD_1V8_D_0: P1.5 U13.5(BCB5) U13.10(BCB0) U14.47(1A1)
LCD_1V8_D_1: P1.8 U13.4(BCB6) U13.9(BCB1) U14.46(1A2)
LCD_1V8_D_2: P1.4 P1.7 U13.3(BCB7) U13.8(BCB2) U14.44(1A3)
LCD_1V8_D_3: P1.3 P2.15 U13.2(BCB8) U13.7(BCB3) U14.43(1A4)
LCD_1V8_D_4: P1.6 P2.9 U13.1(BCB9) U13.6(BCB4) U14.41(1A5)
LCD_1V8_D_5: P1.10 U13.32(GY4) U14.40(1A6)
LCD_1V8_D_6: P1.16 U13.31(GY5) U14.38(1A7)
LCD_1V8_D_7: P1.9 U13.30(GY6) U13.36(GY0) U14.37(1A8)
LCD_1V8_D_8: P2.10 U13.29(GY7) U13.35(GY1) U14.36(2A1)
LCD_1V8_D_9: P1.12 P2.11 U13.28(GY8) U13.34(GY2) U14.35(2A2)
LCD_1V8_D_10: P2.7 P2.13 U13.27(GY9) U13.33(GY3) U14.33(2A3)
LCD_1V8_D_11: P1.13 U13.13(RCR0) U13.18(RCR5) U14.32(2A4)
LCD_1V8_D_12: P2.3 U13.14(RCR1) U13.19(RCR6) U14.30(2A5)
LCD_1V8_D_13: P2.4 P2.8 U13.15(RCR2) U13.20(RCR7) U14.29(2A6)
LCD_1V8_D_14: P1.14 P2.5 U13.16(RCR3) U13.21(RCR8) U14.27(2A7)
LCD_1V8_D_15: P1.11 P2.6 U13.17(RCR4) U13.22(RCR9) U14.26(2A8)
LCD_AC_ENB_CSN: U7.R5(LCD_AC_ENB_CSN/GPIO6[0]) U12.6(B2)
LCD_AC_ENB_CSN_1V8: P2.17 R100.1 U12.3(A2) U13.23(\B\L\A\N\K)
LCD_BLUE: C113.1 C115.2 J8.3 L6.2
LCD_BLUE_N: C113.2 C114.2 L6.1 R122.1 U13.45(ABPB)
LCD_GREEN: C105.1 C109.2 J8.2 L4.2
LCD_GREEN_N: C105.2 C108.2 L4.1 R118.2 U13.41(AGY)
LCD_HSYNC/MMCSD1_D5: U7.H4(MMCSD1_D5/LCD_HSYNC/GPIO8[9]) U15.7(B1) U24.7(B1)
LCD_HSYNC_1V8: P2.18 U24.2(A1)
LCD_HSYNC_5V: J8.13 U15.2(A1)
LCD_PCLK/MMCSD1_D7: U7.F1(MMCSD1_D7/LCD_PCLK/GPIO8[11]) U12.7(B1)
LCD_PCLK_1V8: P2.16 U12.2(A1) U13.26(CLK)
LCD_RED: C110.1 C112.2 J8.1 L5.2
LCD_RED_N: C110.2 C111.2 L5.1 R119.2 U13.43(ARPR)
LCD_SCL: P2.14 U25.5(A1)
LCD_SDA: P1.15 U25.4(A2)
LCD_VSYNC/MMCSD1_D4: U7.G4(MMCSD1_D4/LCD_VSYNC/GPIO8[8]) U15.6(B2) U24.6(B2)
LCD_VSYNC_1V8: P1.17 U24.3(A2)
LCD_VSYNC_5V: J8.14 U15.3(A2)
LED3: Q6.2(5) R101.2 U7.R17(UHPI_HRDY/GPIO6[13])
LED4: Q6.5 R102.2 U7.R16(UHPI_HINTN/GPIO6[12])
LINKLED: J13.9(GRNC) R189.1 U23.2(LED2/NINTSEL)
MIC_BIAS: R150.1 R151.1 U22.13(MICBIAS)
MIC_DET: C175.2 J11.2(TIP) R151.2 U22.12(MICDET)
MIC_LEFT: C175.1 U22.11(MIC3L)
MIC_RIGHT: C173.1 U22.14(MIC3R)
MMCSD0_CLK: J4.5(CLOCK) R47.2 U7.E9(EMA_A_23/MMCSD0_CLK/GPIO4[7])
MMCSD0_CMD: J4.3(CMD) R46.2 U7.A10(EMA_A_22/MMCSD0_CMD/GPIO4[6])
MMCSD0_D0: J4.7(DAT0) R48.2 U7.B10(EMA_A_21/MMCSD0_D0/GPIO4[5])
MMCSD0_D1: J4.8(DAT1) R49.2 U7.A11(EMA_A_20/MMCSD0_D1/GPIO4[4])
MMCSD0_D2: J4.1(DAT2) R45.2 U7.C10(EMA_A_19/MMCSD0_D2/GPIO4[3])
MMCSD0_D3: J4.2(CD/DAT3) R50.2 U7.E11(EMA_A_18/MMCSD0_D3/GPIO4[2])
MMCSD0_D4: J15.5(3) U7.B11(EMA_A_17/MMCSD0_D4/GPIO4[1])
MMCSD0_D6: J15.9(5) U7.C11(EMA_A_15/MMCSD0_D6/GPIO5[15])
MMCSD0_D7: J15.11(6) U7.A12(EMA_A_14/MMCSD0_D7/GPIO5[14])
MMCSD1_CLK: J15.14(27) U7.G2(MMCSD1_CLK/UPP_CH0_START/GPIO8[)
MMCSD1_CMD: J15.12(26) U7.J4(MMCSD1_CMD/UPP_CH0_ENABLE/GPIO8)
MMCSD1_D0: J15.4(22) U7.G1(MMCSD1_D0/UPP_CH0_CLK/GPIO8[15])
MMCSD1_D1: J15.6(23) U7.J3(VPIF_CLKIN3/MMCSD1_D1/GPIO6[2])
MMCSD1_D2: J15.8(24) U7.K3(VPIF_CLK02/MMCSD1_D2/GPIO6[3])
MMCSD1_D3: J15.10(25) U7.H3(VPIF_CLKIN2/MMCSD1_D3/GPIO6[4])
NMIN: R59.2 U7.J17(NMIN)
OSCI: U8.27(OSCI)
OSCIN: R43.2 R264.1 U7.L19(OSCIN)
OSCO: U8.28(OSCO)
PER_IN_MODE: R13.1 R16.2 U3.23(MODE)
PHP_RSTN: J15.18(29) J16.33 P1.18 R41.1 U9.12(R\S\T\) U11.4(Y) U21.34(RESETB) U22.33(R\E\S\E\T\) U23.19(NRST) U27.1(OE)
PM_1V2N: JP4.2 R5.4(SENS2)
PM_1V2P: JP4.1 R5.3(SENS1)
PM_1V8N: JP2.2 R2.4(SENS2)
PM_1V8P: JP2.1 R2.3(SENS1)
PM_3V3N: JP3.2 R4.4(SENS2)
PM_3V3P: JP3.1 R4.3(SENS1)
PWR_FAILN: R15.2 TP9.1 U3.21(P\W\R\F\A\I\L\)
PWRFAIL_SNS: R12.1 R14.2 U3.30(PWRFAIL_SNS)
RESET#: U8.18(RESET#)
RI#: U8.3(RI#)
RTC_CVDD: R29.2 R31.1 U7.L14(RTC_CVDD)
RTC_VSS: C84.2 C85.2 U7.H18(RTC_VSS)
RTC_XI: C85.1 U7.J19(RTC_XI) Y2.1
RTC_XOUT: C84.1 U7.H19(RTC_XO) Y2.2
RTCK: J6.9 R269.1
RTS#: U8.32(RTS#)
SATA_REF_CLKN: C46.2 U7.N1(SATA_REFCLKN)
SATA_REF_CLKN_K: C46.1 U9.5(OUTN)
SATA_REF_CLKP: C34.2 U7.N2(SATA_REFCLKP)
SATA_REF_CLKP_K: C34.1 U9.6(OUTP)
SATA_RXN: C92.2 J7.5
SATA_RXP: C93.2 J7.6
SATA_TXN: C90.2 J7.3
SATA_TXP: C91.2 J7.2
SPI0_CLK/EPWM0_A/MII_RXCLK: R178.1 R216.2 R276.2 U7.D19(SPI0_CLK/EPWM0_A/GPIO1[8]/MII_R)
SPI0_ENAN/EPWM0_B/MII_RXDV: R177.1 R217.2 U7.C17(SPI0_ENAN/EPWM0_B/MII_RXDV)
SPI0_SCSN_0/MDIO_D: R169.2 U7.D17(SPI0_SCSN_0/TIMER64P1_OUT12/GPI) U23.16(MDIO)
SPI0_SCSN_1/MDIO_CLK: R171.2 U7.E16(SPI0_SCSN_1/TIMER64P0_OUT12/GPI) U23.17(MDC)
SPI0_SCSN_2/UART0_RTSN/MII_RXD0: R175.1 R278.2 U7.D16(SPI0_SCSN_2/UART0_RTSN/GPIO8[1])
SPI0_SCSN_3/UART0_CTSN/MII_RXD1: R174.1 R279.2 U7.E17(SPI0_SCSN_3/UART0_CTSN/GPIO8[2])
SPI0_SCSN_4/UART0_TXD/MII_RXD2: R173.1 R218.2 U7.D18(SPI0_SCSN_4/UART0_TXD/GPIO8[3]/)
SPI0_SCSN_5/UART0_RXD/MII_RXD3: R172.1 R219.2 R277.2 U7.C19(SPI0_SCSN_5/UART0_RXD/GPIO8[4]/)
SPI0_SIMO/EPWM0_SYNCO/MII_CRS: R184.1 R214.2 U7.C18(SPI0_SIMO/EPWM0_SYNCO/GPIO8[5]/)
SPI0_SOMI/EPWM0_SYNCI/MII_RXERR: R179.1 R215.2 R275.2 U7.C16(SPI0_SOMI/EPWM0_SYNCI/GPIO8[6]/)
SPI1_CLK: J16.32 R200.1 U7.G19(SPI1_CLK/GPIO2[13])
SPI1_SCSN_0/EPWM1B: J15.44 U7.E19(SPI1_SCSN_0/EPWM1_B/GPIO2[14]/T)
SPI1_SCSN_1/EPWM1A: J15.40 U7.F18(SPI1_SCSN_1/EPWM1_A/GPIO2[15]/T)
SPI1_SCSN_2/UART1_TXD: R205.1 R206.1 U7.F19(SPI1_SCSN_2/UART1_TXD/SATA_CP_P)
SPI1_SCSN_3: J16.34 R208.2
SPI1_SCSN_3/UART1_RXD: R208.1 R209.1 U7.E18(SPI1_SCSN_3/UART1_RXD/SATA_LED/)
SPI1_SCSN_4/UART2_TXD/I2C1_SDA: R97.2 U7.F16(SPI1_SCSN_4/UART2_TXD/I2C1_SDA/) U8.2(RXD)
SPI1_SCSN_5/UART2_RXD/I2C1_SCL: R96.2 U7.F17(SPI1_SCSN_5/UART2_RXD/I2C1_SCL/) U8.30(TXD)
SPI1_SCSN_6/I2C0_SDA: J15.15(8) J16.30 R89.2 R146.1 R202.1 U7.G18(SPI1_SCSN_6/I2C0_SDA/TIMER64P3_) U16.4(A2) U21.29(SDA) U22.2(SDA) U25.1(B2)
SPI1_SCSN_7/I2C0_SCL: J15.13(7) J16.29 R86.2 R147.2 R201.1 U7.G16(SPI1_SCSN_7/I2C0_SCL/TIMER64P2_) U16.5(A1) U21.28(SCL) U22.1(SCL) U25.8(B1)
SPI1_SIMO: J16.36 U7.G17(SPI1_SIMO/GPIO2[10]) U26.D4(DR)
SPI1_SOMI: J16.31 R204.1 U7.H17(SPI1_SOMI/GPIO2[11])
SPIO_CLK: J15.25(13) R216.1
SPIO_ENAN: J15.27(14) R217.1
SPIO_SIMO: J15.21(11) R214.1
SPIO_SOMI: J15.23(12) R215.1
TCK: R58.2 R271.1 U7.J15(TCK)
TCT_RCT: C198.1 J13.3(TCT) J13.6(RCT) R185.1
TDI: J6.3 R55.2 U7.M16(TDI)
TDO: J6.7 R272.1
TMS: J6.1 R57.2 U7.L16(TMS)
TRSTN: J6.2 R61.1 U7.L17(TRSTN)
TS_INT: P2.12 U28.3(A)
TXD0_K: R90.1 U7.F3(AXR0/ECAP0_APWM0/GPIO8[7]/MII_T)
TXD1_K: R93.1 U7.E1(AXR1/MCBSP0_DX0/GPIO1[9]/MII_TX)
TXD2_K: R92.1 U7.E2(AXR2/MCBSP0_DR0/GPIO1[10]/MII_T)
TXD3_K: R91.1 U7.E3(AXR3/MCBSP0_FSX0/GPIO1[11]/MII_)
UART0_RX: J15.31(16) R219.1
UART0_TX: J15.29(15) R218.1
UART1_RXD: J15.17(9) R209.2
UART1_TXD: J15.19(10) R206.2
USB0_DN: J2.2(D-) U7.M18(USB0_DM)
USB0_DP: J2.3(D+) U7.M19(USB0_DP)
USB0_ID: J2.4(ID) JP1.2 U7.P16(USB0_ID)
USB1_DN: J5.2(P2) U7.P18(USB1_DM)
USB1_DP: J5.3(P3) U7.P19(USB1_DP)
USB_DRVVBUSN: R51.2 R52.1 U6.2(A) U7.K18(USB0_DRVVBUSN)
USB_UART_DN: J3.2(D-) U8.15(USBDM)
USB_UART_DP: J3.3(D+) U8.14(USBDP)
VDCDC1: L2.1 R4.2(I2) U3.8(VDCDC1)
VDCDC2: L1.2 R2.1(I1) U3.25(VDCDC2)
VDCDC3: L3.2 R5.1(I1) R6.2 U3.1(VDCDC3)
VDECODE_CLKOUT: R141.1 U21.40(DATACLK) U27.2(A)
VPIF_CLKIN1: R81.1 U7.V15(VPIF_CLKIN1/UHPI_HDS1N/GPIO6[6])
VPIF_DOUT0/LCD_D_0: U7.W1(VPIF_DOUT0/LCD_D_0/UPP_XD8/GPIO) U14.2(1B1)
VPIF_DOUT1/LCD_D_1: U7.W2(VPIF_DOUT1/LCD_D_1/UPP_XD9/GPIO) U14.3(1B2)
VPIF_DOUT2/LCD_D_2: U7.W3(VPIF_DOUT2/LCD_D_2/UPP_XD10/GPI) U14.5(1B3)
VPIF_DOUT3/LCD_D_3: U7.V1(VPIF_DOUT3/LCD_D_3/UPP_XD11/GPI) U14.6(1B4)
VPIF_DOUT4/LCD_D_4: U7.V2(VPIF_DOUT4/LCD_D_4/UPP_XD12/GPI) U14.8(1B5)
VPIF_DOUT5/LCD_D_5: U7.V3(VPIF_DOUT5/LCD_D_5/UPP_XD13/GPI) U14.9(1B6)
VPIF_DOUT6/LCD_D_6: U7.U1(VPIF_DOUT6/LCD_D_6/UPP_XD14/GPI) U14.11(1B7)
VPIF_DOUT7/LCD_D_7: U7.U2(VPIF_DOUT7/LCD_D_7/UPP_XD15/GPI) U14.12(1B8)
VPIF_DOUT8/LCD_D_8: R85.2 R263.2 U7.U3(VPIF_DOUT8/LCD_D_8/UPP_XD0/GPIO) U14.13(2B1)
VPIF_DOUT9/LCD_D_9: R80.2 SW1.4(A4) U7.T1(VPIF_DOUT9/LCD_D_9/UPP_XD1/GPIO) U14.14(2B2)
VPIF_DOUT10/LCD_D_10: R74.2 SW1.3(A3) U7.T2(VPIF_DOUT10/LCD_D_10/UPP_XD2/GP) U14.16(2B3)
VPIF_DOUT11/LCD_D_11: R73.1 SW1.2(A2) U7.T3(VPIF_DOUT11/LCD_D_11/UPP_XD3/GP) U14.17(2B4)
VPIF_DOUT12/LCD_D_12: R75.1 SW1.1(A1) U7.R1(VPIF_DOUT12/LCD_D_12/UPP_XD4/GP) U14.19(2B5)
VPIF_DOUT13/LCD_D_13: R82.2 R252.2 U7.R2(VPIF_DOUT13/LCD_D_13/UPP_XD5/GP) U14.20(2B6)
VPIF_DOUT14/LCD_D_14: R83.2 R261.2 U7.R3(VPIF_DOUT14/LCD_D_14/UPP_XD6/GP) U14.22(2B7)
VPIF_DOUT15/LCD_D_15: R84.2 R262.2 U7.P4(VPIF_DOUT15/LCD_D_15/UPP_XD7/GP) U14.23(2B8)
VS/BLK/GPIO: TP13.1 U21.73(VS/VBLK/GPIO)
XTAL1: C142.1 R142.1 U21.74(XTAL1) Y4.1
XTAL2: R142.2 R144.2 U21.75(XTAL2)
N16780199: R113.1 U13.47(M1)
N16780460: R114.1 U13.48(M2)
N16782098: R99.1 U13.25(SYNC_T)
N16782372: R98.1 U13.24(\S\Y\N\C)
N16792303: C107.2 U13.39(COMP)
N16794587: C116.2 U13.37(VREF)
N16803294: R117.1 U13.38(FSADJ)
N16951647: C147.1 C148.1 FB9.2 U21.4(CH1_A33VDD) U21.5(CH2_A33VDD)
N16958510: C157.1 C158.1 FB10.2 U21.11(CH2_A18VDD) U21.12(A18VDD_REF) U21.25(A18VDD) U21.76(PLL_A18VDD) U21.78(CH1_A18VDD)
N16963689: C160.1 U21.1(VI_1_B)
N16963693: C159.1 U21.80(VI_1_A)
N16963722: C161.1 U21.2(VI_1_C)
N16970911: C168.1 U21.18(VI_3_C)
N16970913: C167.1 U21.17(VI_3_B)
N16970940: C169.1 U21.23(VI_4_A)
N16971321: C166.1 U21.16(VI_3_A)
N16980937: C165.1 U21.9(VI_2_C)
N16980978: C164.1 U21.7(VI_2_A)
N16984417: C162.2 U21.8(VI_2_B)
N16987290: C162.1 C163.1 FB11.2 R273.1
N16998043: C143.1 R144.1 Y4.2
N17013995: R143.2 U21.33(PWDN)
N17016505: R145.2 U21.71(FID/GPIO)
N17141238: R163.2 Y5.1(EN)
N17232839: TP16.1 U22.35(GPIO1)
N17232859: TP17.1 U22.34(GPIO2)
N17232911: C179.1 U22.31(RIGHT_LO+)
N17232927: C178.1 U22.29(LEFT_LO+)
N17232971: R158.2 U22.46(MFP1)
N17232975: R159.2 U22.45(MFP0)
N17235121: R160.1 R162.2 U22.43(SELECT)
N17236450: C176.1 C177.2 R154.1 R155.2
N17236452: C172.1 C174.2 R152.1 R153.2
N17236454: C172.2 U22.3(LINE1L+)
N17236480: C176.2 U22.5(LINE1R+)
N17236488: J10.3(4U) R152.2
N17236492: J10.2(1U) R154.2
N17245158: R182.2 U23.20(TX_CLK)
N17245537: R184.2 U23.14(CRS)
N17245539: R175.2 U23.11(RXD0/MODE0)
N17245582: R179.2 U23.13(RX_ER/RXD4/PHYAD0)
N17245602: R178.2 U23.7(RX_CLK/PHYAD1)
N17245638: R170.1 R173.2 U23.9(RXD2/RMIISEL)
N17245640: R177.2 U23.26(RX_DV)
N17245742: R183.2 U23.15(COL/CRS_DV/MODE2)
N17245758: R174.2 U23.10(RXD1/MODE1)
N17245773: R172.2 U23.8(RXD3/PHYAD2)
N17258283: R125.1 U17.K9(ODT)
N17393106: C202.2 R190.2 Y6.2
N17400815: R186.1 U23.32(RBIAS)
N17544407: D3.2(ANODE) R9.2
N17548747: S1.1(A1) S1.2(A2) U1.1(M\R\)
N17650320: C26.1 U7.N3(SATA_REG)
N17656359: C25.1 U7.N17(USB0_VDDA12)
N17906579: R139.1 U18.C3(\\W\P)
N18123385: R95.1 U7.B1(ACLKX/GPIO0[14])
N18123387: R94.1 U7.B2(AFSX/GPIO0[12])
N18208208: C83.1 R54.1 U7.N19(USB0_VBUS)
N18472217: C144.1 TP18.1 U23.6(VDD_CORE)
N18511755: R187.2 U23.18(NINT/TX_ER/TXD4)
N18783117: R36.2 U9.15(OD2)
N18784485: R35.2 U9.13(OD0)
N18785856: R34.2 U9.11(OS0)
N18803276: R37.1 U9.26(PR1)
N18804657: R38.1 U9.25(PR0)
N18806041: R39.1 U9.14(OD1)
N18807428: R40.1 U9.10(OS1)
N18880116: C47.1 U9.21(XIN) Y1.2
N18892363: C48.2 U9.17(REG_CAP2)
N18895224: C49.2 U9.19(REG_CAP1)
N20179308: R65.2 U11.3(B)
N22409494: J6.11 R271.2
N22965999: BH1.1(P) R31.2
N24724105: R60.2 U7.T18(CLKOUT/UHPI_HDS2N/GPIO6[14])
N24803967: J13.10(GRNA) R176.2
N24819875: J13.13(SHD1) J13.14(SHD2) R180.2
N25060845: FB11.1 J9.2(CENTER)
N26098709: R10.1 U3.18(EN_DCDC3)
N26107809: L2.2 U3.6(L1)
N26126911: L1.1 U3.27(L2)
N26141295: L3.1 U3.3(L3)
N26148986: R6.1 R8.1 U3.32(DEFDCDC3)
N26169371: FB1.2 U3.13(AGND2) U3.31(AGND1) U3.33(TER_PAD)
N26269870: U4.9(E\N\4\) U6.4(Y)
N26409188: R3.2 U3.29(VCC)
N26417389: R11.1 U3.17(EN_LDO)
N26426042: R7.1 U3.24(EN_VDD_ALIVE)
N26578476: Q1.1(BASE) Q3.3(COLLECTOR) R24.1
N26578488: Q3.1(BASE) R27.2
N26585213: Q2.1(BASE) Q4.3(COLLECTOR) R26.1
N26585231: Q4.1(BASE) R28.2
N27037804: R42.1 U9.7(CE)
N27170750: R19.2 R20.2 U3.11(FB_LDO1)
N27170752: R17.2 R18.1 U3.10(FB_LDO2)
N27473148: C173.2 J11.3(RING) R150.2
N27493630: C20.1 C21.1 R30.1 U8.1(VCCIO) U8.16(3V3OUT)
N27494415: C22.1 C23.1 FB2.1 U8.19(VCC)
N27494781: C24.1 FB2.2 J3.1(VB)
N27611173: J16.28 R199.1
N27611176: J16.27 R198.1
N27655467: C211.2 U26.D1(CAP_D)
N27655536: C212.2 U26.D2(CAP_IO)
N27655572: C213.2 U26.B2(CAP_A)
N27655608: C214.2 U26.A4(VMXOUT)
N27658869: R203.2 R207.1 U26.C1(IOSEL)
N27689876: J13.12(YELA) R181.2
N27790142: D2.1(CATHODE) R1.2
N27790158: R1.1 R270.2 U2.3(F\L\A\G\)
N27799298: R33.1 U7.U12(DDR_ZP)
N27851951: R30.2 U8.11(CBUS3)
N27881562: C90.1 U7.J2(SATA_TXN)
N27882349: C91.1 U7.J1(SATA_TXP)
N27882474: C92.1 U7.L2(SATA_RXN)
N27882599: C93.1 U7.L1(SATA_RXP)
N28002926: R43.1 Y3.3(OUTPUT)
N28068081: D6.2(ANODE) R210.2
N28068095: D6.1(CATHODE) Q5.6(3)
N28068166: D7.2(ANODE) R211.2
N28068180: D7.1(CATHODE) Q5.3
N28115819: D5.2(ANODE) R87.1
N28153433: R223.1 S3.1(A1) S3.2(A2)
N28153568: R222.1 S2.1(A1) S2.2(A2)
N28157154: R76.2 SW1.16(B1)
N28157182: R77.2 SW1.15(B2)
N28157237: R78.2 SW1.14(B3)
N28157266: R79.2 SW1.13(B4)
N28226673: R253.2 SW1.12(B5)
N28226728: R256.2 SW1.9(B8)
N28226757: R255.2 SW1.10(B7)
N28226786: R254.2 SW1.11(B6)
N28488580: D8.2(CATHODE) R268.2 TP19.1(TP) TP20.1(TP)
N28488978: R268.1 U26.B5(FDRV)
N28544289: R269.2 U7.K17(RTCK/GPIO8[0])
N28544350: R272.2 U7.J18(TDO)
N28561453: R274.2 U21.69(C_1/GPIO)
N28567458: J6.5 R64.1
N200921000: D4.2(ANODE) R88.1
N281146221: D4.1(CATHODE) Q6.6(3)
N281146431: D5.1(CATHODE) Q6.3

Pads without a net: D1 2; J3 4; J8 4 11; J16 7 35 37 38 39 40; NOREF#9 1; NOREF#11 1; NOREF#12 1; NOREF#13 1; NOREF#15 1; NOREF#16 1; NOREF#22 1; NOREF#25 1; NOREF#26 1; NOREF#27 1; P2 1; U1 4 5 6 8; U4 2 4 12 15 16; U5 5; U6 1; U7 A2 A18 C2 D10 D11 F4 K4 K19 M3 M14 N16 T16 U19; U8 5 12 13 23 25 29; U9 1 2 3 8 23 24 27 28 29 30 31 32; U17 A2 A8 E2 E8 R3 R7; U18 A1 A2 A9 A10 B1 B9 B10 D6 D7 D8 E3 E4 E5 E6 E7 E8 F3 F4 F5 F6 F8 G3 G5 G8 L1 L2 L9 L10 M1 M2 M9 M10; U21 14 15 19 20 21 22 53 54 57 58 59 60 63 64 65 66 70; U22 4 6 7 8 9 10 18 19 22 23 27 28 30 32 47 48; U26 A5 B1 B3 B4 C5 E1

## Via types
v1: diameter 0.457, hole 0.203, TOP to BOTTOM, 1275 vias
v2: diameter 0.635, hole 0.305, TOP to BOTTOM, 95 vias
v3: diameter 0.61, hole 0.305, TOP to BOTTOM, 5 vias

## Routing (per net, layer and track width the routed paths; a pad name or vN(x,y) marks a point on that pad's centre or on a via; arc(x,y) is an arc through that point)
1V2_LDO: length 80.9
  TOP w0.254: v1(27.94,67.82) 27.94,69.3 U3.16 ; U7.P2 v1(57.36,44.9) U7.P1 ; v1(59.76,44.9) U7.M2 ; v1(58.16,43.3) U7.N4 ; v1(59.76,36.9) U7.M12
  TOP w0.457: R20.1 22.86,70.36 22.28,69.77 22.28,67.82 22.53,67.56 27.69,67.56 v1(27.94,67.82) ; C66.1 66.36,23.18 C69.1 FB4.1 62.1,22.42 v1(62.1,22.1)
  LYR3 w0.457: v1(45.59,57.87) 44.87,57.15 32.77,57.15 v1(27.43,62.48)
  LYR4 w0.381: v1(59.76,30.5) 60.58,29.68 60.58,29.08 61.53,28.13 61.53,25.59 62.1,25.02 v1(62.1,22.1)
  BOTTOM w0.381: v1(58.16,43.3) 58.17,43.29 58.17,43.18 58.85,42.5 C67.1
  BOTTOM w0.457: v1(57.36,44.9) C68.1 57.91,47.19 58.17,47.45 58.17,49.91 56.52,51.56 47.75,51.56 46.23,53.09 46.23,57.24 v1(45.59,57.87) ; v1(27.43,62.48) 27.43,64.01 27.18,64.26 27.18,65.79 27.43,66.04 C17.1 28.19,67.56 v1(27.94,67.82)
1V8_LDO: length 73.3
  TOP w0.254: U7.N14 v1(58.16,34.5) U7.P14 ; v1(57.36,44.1) U7.P3 ; 26.55,70.37 U3.14
  TOP w0.457: C16.2 v1(25.4,68.33) 26.16,69.09 26.16,69.98 26.55,70.37 ; R18.2 v1(21.84,73.41)
  LYR3 w0.457: v1(31.24,61.72) 32.77,60.2 44.45,60.2 v1(44.7,59.94)
  LYR4 w0.457: v1(25.4,68.33) 25.4,69.85 v1(21.84,73.41)
  BOTTOM w0.381: 57.43,44.17 57.94,44.68 ; C65.1 v1(58.16,34.5)
  BOTTOM w0.457: 58.96,47.19 58.96,50.13 56.77,52.32 48.26,52.32 46.99,53.59 46.99,57.66 v1(44.7,59.94) ; 58.96,47.19 C64.1 v1(59.76,46.5) 58.96,46.5 ; 58.96,47.19 58.96,46.5 ; v1(57.36,44.1) 57.43,44.17 ; 58.96,46.5 58.96,45.7 57.94,44.68 ; v1(31.24,61.72) 32,62.48 32,68.07 30.99,69.09 26.92,69.09 26.16,68.33 v1(25.4,68.33)
5V_IN: length 338.8
  TOP w0.457: J16.4 53.71,16.76 54.21,16.26 J16.5 v1(54.21,13.46) ; D2.2 v1(7.35,88.15)
  LYR4 w0.457: 100.58,29.21 97.16,29.21 J15.33 97.16,26.67 100.58,26.67 ; v1(7.35,88.15) 7.73,88.15 13.72,82.17 J1.1
  LYR4 w1.016: 100.58,12.7 100.58,2.03 99.57,1.02 62.48,1.02 58.17,5.33 58.17,7.62 54.21,11.58 v1(54.21,13.46) ; 100.58,12.7 J15.45 ; 100.58,12.7 100.58,40.64 ; J14.1 J14.2 93.6,70.1 100.58,70.1 ; P1.1 P1.2 1.27,58.8 ; 1.27,58.8 1.27,73.66 7.37,79.76 J1.1 16.76,79.76 17.78,80.77 20.07,80.77 21.34,82.04 23.75,82.04 27.05,85.34 53.34,85.34 55.88,87.88 71.63,87.88 73.91,90.17 99.57,90.17 100.58,89.15 100.58,70.1 ; 1.27,58.8 1.27,56.64 5.33,52.58 5.33,43.18 4.57,42.42 J8.9 ; 100.58,40.64 98.42,40.64 ; 100.58,40.64 100.58,70.1
  BOTTOM w0.381: v1(7.35,88.15) 7.37,88.16 7.37,88.77 8,89.41 R270.1
  BOTTOM w0.457: D1.3 11.79,77.83 J1.1 ; P1.2 P1.1
GND_EARTH: length 101.5
  TOP w0.457: v1(88.9,2.79) 90.23,2.79 J3.8 90.29,2.03 v1(88.9,2.03) ; v1(36.32,88.39) 35.18,88.39 J2.7 35.11,89.15 v1(36.32,89.15) ; v1(23.37,89.15) 24.58,89.15 J2.8 24.51,88.39 v1(23.37,88.39) ; v1(82.55,2.13) 81.06,2.13 J3.7 81.22,2.79 v1(82.55,2.79) ; v1(62.99,90.04) v1(64.01,90.04) 64.01,89.09 FB5.1 62.99,89.09 v1(62.99,90.04)
  TOP w1.27: J2.6 J2.7 ; J2.9 J2.8 ; J3.6 J3.7 ; J3.9 J3.8
  LYR2_GND w0.838: 38.23,89.5 J7.9 ; J7.9 39.45,88.28 ; J7.9 40.67,89.5 ; J7.9 39.45,90.71 ; J7.8 53.5,88.5 ; J7.8 52.28,89.71 ; J7.8 52.28,87.28
  LYR5_PWR w0.838: J7.8 52.28,89.71 ; J7.8 53.5,88.5 ; J7.8 52.28,87.28 ; J7.9 39.45,90.71 ; J7.9 39.45,88.28 ; J7.9 40.67,89.5 ; J7.9 38.23,89.5
  BOTTOM w0.457: v1(57.4,90.04) J4.13 v1(55.37,90.04) 55.12,89.79 55.12,86.11 55.37,85.85 55.88,85.85 56.25,85.48 J4.11 56.25,76.34 56.9,75.69 59.58,75.69 J4.15 J4.16 66.57,75.69 70.1,75.69 70.75,76.34 J4.12 70.75,85.48 71.12,85.85 71.63,85.85 71.88,86.11 71.88,89.79 v1(71.63,90.04) J4.14 v1(69.6,90.04)
VCC_1V2A: length 15.3
  TOP w0.121: 58.96,34.5 59.76,34.5
  TOP w0.254: 59.76,34.5 U7.L15 v1(59.76,33.7) ; U7.N15 58.96,34.5
  TOP w0.457: v1(62.1,26.16) 62.1,25.84 FB4.2
  LYR4 w0.121: 61.21,33.3 60.16,33.3 v1(59.76,33.7) U7.L15 60.91,34.1 60.97,34.04
  LYR4 w0.381: 60.97,34.04 61.21,33.8 61.21,29.34 62.1,28.45 v1(62.1,26.16)
VCC_1V3D: length 78.9
  TOP w0.254: v1(58.96,40.1) U7.N8 ; v1(58.96,40.1) U7.M8 ; v1(58.96,40.1) U7.N7 v1(58.16,40.1) ; v1(58.96,38.5) U7.M9 ; U7.K12 v1(60.56,36.9) U7.L12 ; U7.T19 56.07,30.81 56.07,30.18 56.15,30.11 ; U7.H13 v1(62.96,35.3) U7.G13 ; U7.H14 v1(62.16,35.3) ; v1(62.16,36.9) U7.H11 ; v1(62.16,36.9) U7.J12 ; v1(62.16,36.9) U7.H12 ; U7.G8 v1(63.76,40.1) U7.G7 ; v1(65.36,33.7) U7.E15 ; v1(60.56,40.9) U7.K6 ; v1(62.96,38.5) U7.H10 ; U7.H6 v1(62.16,41.7) U7.J6 ; v1(62.16,40.9) U7.H7 ; U7.E5 v1(65.36,42.5) ; v1(57.76,29.72) 57.78,29.72
  TOP w0.381: v1(57.76,29.72) 56.54,29.72 56.15,30.11
  TOP w0.457: v1(69.36,30.5) 69.36,30.1 v1(67.76,28.5) 67.36,28.5 v1(66.16,29.7) 65.42,28.96 58.55,28.96 57.78,29.72
  LYR3 w0.121: v1(61.36,45.7) 61.36,45.57
  LYR4 w0.457: v1(21.84,74.3) 22.48,74.3 23.11,73.66 TP2.1
  BOTTOM w0.381: v1(62.16,40.9) v1(62.16,41.7) 62.05,41.81 C74.1 ; v1(63.76,40.1) 63.87,39.99 C78.1 ; v1(60.56,36.9) 60.67,37.01 C77.1 ; C77.1 62.05,37.01 v1(62.16,36.9) ; C77.1 C75.1 ; C79.1 58.85,40.59 58.96,40.48 v1(58.96,40.1) v1(58.16,40.1) ; C73.1 v1(57.76,29.72)
  BOTTOM w0.457: v1(61.36,45.7) v1(61.36,46.5) C72.1 ; C76.1 v1(69.36,30.5) ; R27.1 14.73,66.55 15.24,67.06 15.24,71.63 16.26,72.64 18.92,72.64 20.57,74.3 v1(21.84,74.3) ; C71.1 v1(66.16,29.7) ; C80.1 v1(67.76,28.5) ; R29.1 47.24,68.83 ; C70.1 C73.1
VCC_1V8D: length 194.5
  TOP w0.254: v1(22.1,52.58) 21.8,52.28 U13.12 ; v1(60.56,41.7) U7.L6 ; 21.84,61.47 v1(22.86,61.47) ; 21.84,61.47 U25.6 ; 21.84,61.47 U25.3 ; U7.P7 v1(58.16,40.9) U7.N6 ; U21.67 32.74,22.07 v1(33.02,22.35) ; U7.R9 v1(57.36,38.5) U7.P10 ; U24.1 24.33,60.5 v1(24.13,60.71) ; U7.G12 v1(63.76,36.9) U7.G11 U7.G10 ; v1(58.16,35.3) U7.P13 57.68,35.78 57.04,35.78 U7.R13 ; U7.P9 v1(58.16,39.3) U7.P8 ; v1(60.56,42.5) U7.K5 ; v1(41.36,35.3) U17.C1 ; v1(42.93,28.19) 42.85,28.12 U21.41 ; U17.G9 v1(34.16,38.5) ; U12.1 16.71,60.5 v1(16.51,60.71) ; v1(35.76,35.3) U17.C7 ; U14.42 v1(35.35,58.97) ; U17.C9 v1(34.16,35.3) ; U17.E9 v1(34.16,36.9) ; v1(41.36,36.9) U17.E1 ; v1(41.36,38.5) U17.G1 ; U17.G7 v1(35.76,39.3) ; v1(41.36,33.7) U17.A1 ; U21.55 35.85,27.9 v1(35.56,28.19) ; v1(61.36,35.3) U7.J13 ; v1(40.64,58.93) 40.85,59.14 U14.31 ; U7.R8 v1(57.36,40.1) U7.R7 ; U17.J9 v1(34.16,40.9) ; U7.N10 v1(58.16,38.5) U7.N9 ; U17.G3 v1(39.76,38.5) ; v1(41.36,40.9) U17.J1 ; U17.M9 v1(34.16,43.3) ; v1(63.76,35.3) U7.F14 ; U17.A9 v1(34.16,33.7) ; v1(41.36,45.7) U17.R1 ; U17.C3 v1(39.76,35.3) ; U21.31 v1(46.22,20.57) ; v1(62.96,41.7) U7.G6
  TOP w0.457: v1(48.51,27.18) v1(47.5,27.18) ; U28.5 13.72,62.48 12.77,61.53 U28.1 12.75,60.71 v1(11.94,60.71) ; U26.E4 11.7,10.65 v1(10.16,12.19) C207.2 ; U26.A2 13.7,5.01 13.88,4.83 v1(15.49,4.83)
  TOP w0.762: FB15.2 22.1,36.84 22.6,37.34 30.12,37.34 v1(30.56,36.9)
  LYR3 w0.457: 16.25,10.92 16.25,5.58 v1(15.49,4.83) ; 16.25,10.92 11.43,10.92 v1(10.16,12.19) ; 16.25,10.92 17.77,12.45 22.35,12.45 27.3,17.4 30.61,17.4 v1(32.77,19.56)
  BOTTOM w0.381: C38.1 v1(58.16,39.3) ; v1(58.16,39.3) C37.1 ; v1(58.16,39.3) v1(58.16,38.5) ; C36.1 57.47,35.99 v1(58.16,35.3) ; v1(58.16,38.5) v1(57.36,38.5) 57.47,38.61 C37.1 ; v1(58.16,38.5) 58.85,37.81 C39.1 ; v1(58.16,40.9) C35.1 57.47,40.21 v1(57.36,40.1) 57.47,39.99 C37.1 ; v1(63.76,36.9) 63.87,36.79 C44.1 63.87,35.41 v1(63.76,35.3) ; C40.1 61.36,42.75 61.11,42.5 v1(60.56,42.5) v1(60.56,41.7) ; C41.1 v1(61.36,35.3)
  BOTTOM w0.457: R28.1 12.95,69.85 11.18,68.07 11.18,62.48 11.94,61.72 v1(11.94,60.71) C216.2 13.21,59.94 ; v1(34.16,43.3) C120.1 ; C45.1 53.72,23.81 53.72,23.24 54.36,22.61 C42.1 ; C45.1 53.09,24.45 v1(53.09,25.4) ; C45.1 53.85,24.57 v1(53.85,25.4) ; v1(36.07,48.39) 35.38,47.7 v1(35.36,47.7) C124.1 ; v1(41.36,35.3) C133.1 ; C102.2 v1(40.64,58.93) ; C153.1 v1(42.93,28.19) ; C129.1 v1(41.36,40.9) ; v1(46.22,20.57) 45.97,20.83 C155.1 ; 30.96,39.3 32.82,39.3 33.06,39.05 C122.1 v1(34.16,38.5) ; v1(34.16,33.7) 33.07,33.7 C127.1 33.06,34.25 32.82,34.5 30.96,34.5 ; C128.1 42.45,45.7 v1(41.36,45.7) ; v1(34.16,40.9) C121.1 33.06,40.35 32.82,40.1 30.96,40.1 ; v1(33.02,22.35) C154.1 29.97,22.35 ; R123.1 C119.2 36.16,39.7 v1(35.76,39.3) ; R100.2 R98.2 12.95,52.83 12.7,53.09 12.7,53.59 12.45,53.85 R99.2 v1(11.94,55.12) ; 16.51,59.94 v1(16.51,60.71) C94.1 17.27,59.94 ; v1(15.49,4.83) 15.75,4.57 C208.2 ; C135.1 v1(35.76,35.3) ; 30.96,37.7 32.82,37.7 33.06,37.45 C125.1 v1(34.16,36.9) ; C43.1 v1(54.16,27.3) ; C123.1 v1(35.36,31.7) ; FB10.1 v1(41.91,19.05) C156.1 ; v1(22.86,61.47) 22.35,61.47 22.1,61.21 C210.1 22.1,59.94 ; C101.2 35.56,59.18 v1(35.35,58.97) ; C134.1 42.45,33.7 v1(41.36,33.7) ; C132.1 v1(41.36,36.9) ; 30.96,36.1 32.82,36.1 33.06,35.85 C126.1 v1(34.16,35.3) ; 24.89,59.94 C204.1 v1(24.13,60.71) 24.13,59.94 ; C131.1 v1(40.16,47.7) ; 23.62,57.15 23.62,54.1 v1(22.1,52.58) 21.84,52.83 C103.2 ; C130.1 v1(41.36,38.5) ; v1(35.56,28.19) C152.1 ; v1(48.51,27.18) 48.51,27.75 C171.1 47.5,27.75 v1(47.5,27.18) v1(48.51,27.18)
  BOTTOM w0.838: 42.67,62.59 TP4.1 ; TP4.1 41.76,63.5 ; TP4.1 43.59,63.5 ; TP4.1 42.67,64.41
  vias: v1(29.97,25.65) v1(29.97,24.64) v1(29.97,23.62) v1(30.48,28.19) v1(30.56,47.7) v1(30.56,45.7) v1(30.56,43.3) v1(30.56,40.9) v1(30.56,38.5) v1(30.56,35.3) v1(30.56,33.7) v1(30.56,31.7) v1(33.02,28.19) v1(34.29,28.19) v1(36.83,28.19) v1(45.21,25.65) v1(54.99,49.66) v1(54.99,48.9) v1(55.74,48.9) v1(55.75,49.66)
VCC_3V3A: length 46.4
  TOP w0.254: U23.27 76.95,74.41 v1(77.47,74.93) ; U23.1 73.73,73.59
  TOP w0.457: R165.1 v1(74.93,77.47) ; C201.1 72.39,75.18 72.64,74.93 72.96,74.93 v1(73.73,74.17) 73.73,73.59 ; R167.1 v1(76.2,77.47)
  LYR4 w0.457: v1(88.9,84.58) 87.63,83.31 86.36,83.31 81.79,78.74 v1(81.79,73.66)
  BOTTOM w0.457: R185.2 v1(88.9,84.58) ; 77.47,73.66 v1(77.47,74.93) C200.1 ; v1(73.73,74.17) 73.73,76.27 74.17,76.71 R165.1 ; v1(81.79,73.66) 81.79,72.58 FB18.2 80.77,72.58 v1(80.77,73.66) ; R165.1 v1(74.93,77.47) ; R165.1 R167.1 v1(76.2,77.47)
  BOTTOM w0.762: v1(81.79,73.66) v1(80.77,73.66) 78.74,73.66 ; 78.74,73.66 74.68,73.66 74.17,74.17 v1(73.73,74.17) ; 78.74,73.66 C199.1 FB18.2
VCC_3V3ADAC: length 16.8
  TOP w0.254: U13.44 v1(17.26,43.95) ; U13.40 15.26,43.96 v1(15.24,43.94)
  LYR3 w0.762: 17.26,43.18 16,43.18 v1(15.24,43.94) ; 17.26,43.18 v1(17.26,43.95) ; 17.26,43.18 20.07,43.18 v1(20.83,43.94)
  BOTTOM w0.457: C97.2 17.78,44.47 v1(17.26,43.95) ; 20.83,45.21 21.84,45.21 22.1,45.47 22.1,45.97 22.35,46.23 C107.1 ; C98.1 v1(15.24,43.94)
  BOTTOM w0.762: FB6.2 v1(20.83,43.94)
VCC_3V3AFLA: length 26
  TOP w0.254: U18.D3 v1(81.76,53.3) ; U18.H8 v1(76.96,57.3) ; v1(78.56,58.1) U18.J6 ; v1(80.96,56.5) U18.G4
  BOTTOM w0.457: 79.36,57.15 C139.1 78.67,57.99 v1(78.56,58.1) ; R139.2 R137.2 ; C145.1 v1(80.96,56.5) 80.34,55.88 77.22,55.88 76.96,56.13 v1(76.96,57.3) C138.1 ; v1(81.76,53.3) 82.16,53.3 82.45,53.59 C140.1 79.36,54.1
  BOTTOM w0.762: 79.36,57.15 FB8.2
VCC_3V3ASATA: length 17.9
  TOP w0.254: U9.18 v1(58.4,69.32) ; v1(59.69,63.5) 59.62,63.57 U9.9 ; v1(59.69,68.58) 59.62,68.51 U9.16
  LYR4 w0.457: v1(59.69,63.5) v1(59.69,68.58)
  BOTTOM w0.457: FB3.1 57.15,70.57 v1(58.4,69.32) ; C29.1 61.02,71.44 C30.1 59.69,70.61 v1(58.4,69.32) ; C28.1 v1(59.69,63.5) ; C27.1 v1(59.69,68.58) 59.14,68.58 v1(58.4,69.32)
VCC_3V3D: length 235
  TOP w0.254: U14.18 40.85,53.89 v1(40.64,54.1) ; U7.F5 v1(63.76,41.7) U7.G5 ; 25.65,46.48 U16.6 ; 25.65,46.48 v1(26.67,46.48) ; 25.65,46.48 U16.3 ; R193.2 48.77,22.86 47.24,22.86 46.48,23.62 v1(46.23,23.62) 45.78,24.07 U21.38 ; U25.7 21.34,62.74 21.08,62.48 v1(20.32,62.48) ; U7.F12 v1(64.56,36.9) U7.F11 ; v1(16.51,63.25) 16.71,63.45 U12.8 ; v1(58.16,31.3) U7.N18 ; v1(24.13,53.34) 24.33,53.54 U15.8 ; v1(56.64,62.74) 56.9,63 U9.4 ; v1(64.56,38.5) U7.F10 ; U9.20 v1(57.4,69.34) ; U7.R4 U7.P5 v1(58.16,41.7) U7.P6 ; U14.7 v1(35.35,54.1) ; v1(62.16,34.5) U7.J14 U7.K15 ; U7.F6 v1(64.56,40.9) U7.F7 ; v1(59.76,43.3) U7.L4 ; U7.F13 v1(64.56,35.3) U7.E14 v1(64.56,34.5) U7.F15 ; U7.G14 U7.G15 v1(63.76,33.7) ; U7.J5 v1(62.16,42.5) U7.H5 ; U7.K13 v1(60.56,36.1) U7.L13 ; v1(31.75,25.65) 31.5,25.4 U21.61 ; U7.P12 v1(58.16,36.1) U7.N13 v1(58.96,35.3) U7.M13 ; U21.48 39.35,25.89 v1(38.86,25.4) ; U24.8 24.33,63.45 v1(24.13,63.25) ; v1(64.56,40.1) U7.F8 ; U23.12 v1(75.95,67.57) ; v1(58.16,33.7) U7.P15 ; U7.G9 v1(63.76,38.5)
  TOP w0.457: R63.1 v1(77.47,33.02) ; R35.1 v1(63.5,66.55) ; v1(57.4,80.52) R44.1 ; R64.2 v1(81.28,25.4) ; R36.1 v1(63.5,68.58) ; v1(53.09,20.32) R192.2 R194.2 ; R62.1 v1(81.28,33.02) ; R58.1 v1(80.01,31.75) ; R34.1 v1(63.5,64.52) ; U28.6 12.75,63.25 v1(11.94,63.25) ; v1(43.18,83.06) 43.18,84.58 42.93,84.84 R51.1 ; U26.E5 10.67,9.65 v1(9.91,9.65) ; v1(52.21,13.46) J16.1 52.21,16.4 52.71,16.9 J16.2 ; v1(61.21,88.9) R46.1 R50.1 R45.1 C82.1 v1(57.4,88.9) ; R65.1 v1(77.47,29.21) ; v1(67.06,88.9) R47.1 R48.1 R49.1 ; U11.5 v1(74.93,35.56) ; C4.1 v1(57.4,85.09) ; J16.3 v1(53.21,13.46) ; R41.2 v1(63.5,65.53) ; R163.1 C180.1 v1(22.61,26.42) ; R55.1 v1(81.28,21.59) ; v1(68.07,22.86) R97.1 R96.1 ; R57.1 v1(80.01,24.13) ; U1.2 v1(60.33,80.01) ; C81.1 v1(54.1,84.77) ; v1(18.03,19.81) v1(17.02,19.81) 17.02,20.64 FB14.2 18.03,20.64 v1(18.03,19.81)
  LYR4 w0.381: v1(58.96,35.3) v1(58.16,36.1)
  LYR5_PWR w0.838: TP5.1 72.03,21.59 ; TP5.1 71.12,20.68 ; TP5.1 70.21,21.59 ; TP5.1 71.12,22.5 ; 98.42,67.61 98.42,68.58 ; 98.42,68.58 99.39,68.58 ; 98.42,68.58 98.42,69.55 ; 98.42,68.58 97.46,68.58 ; 88.57,15.24 J14.43 ; J14.43 89.53,14.27 ; J14.43 89.53,16.21 ; J14.43 90.5,15.24 ; J15.1 95.89,69.55 ; J15.1 96.85,68.58 ; J15.1 95.89,67.61 ; J15.1 94.92,68.58 ; 92.08,14.27 J14.44 ; J14.44 92.08,16.21 ; J14.44 91.11,15.24 ; J14.44 93.04,15.24
  BOTTOM w0.254: C50.1 64.21,29.01 64.34,28.88 64.34,28.12 64.47,27.99 R59.1
  BOTTOM w0.381: C53.1 v1(60.56,36.1) ; C59.1 59.87,43.41 v1(59.76,43.3) ; 64.56,37.7 v1(64.56,38.5) v1(63.76,38.5) 63.87,38.39 C62.1 64.56,37.7 ; 64.56,37.7 v1(64.56,36.9) v1(64.56,35.3) v1(64.56,34.5) C61.1 63.87,33.81 v1(63.76,33.7) ; v1(58.16,36.1) 58.16,36.9 57.47,37.59 C52.1 ; v1(58.96,35.3) 58.96,34.61 C55.1 ; v1(64.56,40.1) v1(64.56,40.9) C57.1 63.87,41.59 v1(63.76,41.7) ; C58.1 v1(62.16,42.5) ; C51.1 58.16,41.81 v1(58.16,41.7)
  BOTTOM w0.457: 58.77,24.13 58.17,24.13 57.66,24.64 C86.1 v1(57.15,25.4) ; 58.77,24.13 Y3.1 ; 58.77,24.13 Y3.4 ; R171.1 79.38,65.53 ; 79.38,65.53 79.38,64.52 79.88,64.01 v1(80.01,64.01) ; 79.38,65.53 R169.1 ; R89.1 v1(66.29,16.51) ; v1(66.29,16.51) 67.06,16.51 67.31,16.26 R147.1 ; v1(66.29,16.51) R86.1 ; R88.2 v1(75.95,43.69) ; C50.1 v1(63.76,29.7) ; R260.2 v1(68.58,57.91) ; FB14.2 16.45,21.15 16,21.59 C185.1 ; FB14.2 17.02,20.64 v1(17.02,19.81) v1(18.03,19.81) 18.03,20.64 FB14.2 ; C54.1 v1(58.96,29.7) ; v1(57.4,69.34) 57.66,69.08 C31.1 ; C193.1 75.69,67.83 v1(75.95,67.57) 76.2,67.32 R278.1 ; v1(57.4,88.9) 57.28,88.78 J4.4 ; C217.1 v1(11.94,63.25) ; R141.2 v1(56.13,16.51) ; C151.1 v1(46.23,23.62) ; R275.1 R278.1 ; R278.1 R279.1 ; C96.2 FB6.1 ; C100.2 v1(40.64,54.1) ; C215.1 v1(50.8,13.46) ; R245.1 v1(63.25,16.51) R244.1 ; v1(26.67,46.48) 26.16,46.48 25.91,46.23 C118.1 ; R247.1 v1(62.23,16.51) R246.1 ; C146.1 v1(34.29,19.05) FB9.1 ; v1(78.23,48.35) FB8.1 v1(80.52,48.35) ; C63.1 v1(67.76,47.7) ; R160.2 15.75,36.07 v1(16,35.81) ; R146.2 42.55,21.21 42.55,22.23 41.91,22.86 v1(41.91,24.64) R148.2 ; C95.2 v1(16.51,63.25) ; R252.1 v1(41.66,57.91) ; U27.5 52.39,13.64 v1(52.21,13.46) ; C206.2 21.08,62.74 20.83,62.48 v1(20.32,62.48) ; v1(35.35,54.1) 35.56,53.89 C99.2 ; R251.1 v1(60.2,16.51) R250.1 ; C205.2 v1(24.13,63.25) ; v1(38.86,25.4) 39.37,25.91 C150.1 ; R276.1 R277.1 v1(72.39,67.31) ; R87.2 v1(80.01,43.69) ; v1(9.91,9.65) 9.91,10.16 9.14,10.92 C209.2 ; C106.2 v1(24.13,53.34) ; R203.1 v1(19.05,8.38) ; R258.2 v1(64.77,57.91) ; R103.1 v1(71.76,31.7) ; R106.1 v1(71.76,32.9) ; v1(57.66,74.68) 57.4,74.68 57.15,74.42 FB3.2 C33.1 ; R104.1 v1(71.76,40.1) ; R221.1 v1(95.76,7.62) ; R257.1 v1(66.04,57.91) ; R80.1 v1(57.15,57.91) ; R280.1 v1(81.28,67.56) ; R259.1 v1(67.31,57.91) ; R73.2 v1(53.34,57.91) ; C149.1 v1(31.75,25.65) ; R105.1 v1(71.76,34.1) ; C32.1 v1(56.64,62.74) ; R189.2 72.26,73.03 71.88,73.41 71.88,74.17 v1(71.12,74.93) ; R220.1 v1(6.1,19.3) ; R74.1 v1(55.88,57.91) ; Y5.4 24.13,26.67 23.88,26.42 v1(22.61,26.42) ; R176.1 v1(88.39,71.12) ; R261.1 v1(39.62,57.91) ; R75.2 v1(50.8,57.91) ; R248.1 v1(61.21,16.51) R249.1 ; R263.1 v1(37.59,57.91) ; R262.1 v1(43.69,57.91) ; C60.1 v1(69.36,37.7) ; C56.1 v1(69.36,36.5) ; v1(28.32,79.76) 28.32,78.8 C13.1 27.56,78.8 v1(27.56,79.76) v1(28.32,79.76)
  BOTTOM w0.762: FB18.1 v1(81.28,68.58) v1(81.28,67.56) ; FB6.1 21.91,47.18 v1(22.1,46.99)
  BOTTOM w0.889: R4.1 24.08,78.42 C14.1 C13.1
